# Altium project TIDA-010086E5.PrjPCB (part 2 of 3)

## Sheet TIDA-010086E5_ControlCard.SchDoc
size 431 x 279 mm; Date: Not shown in title block; ApprovedBy: Not shown in title block; CheckedBy: Not shown in title block; Author: Not shown in title block; CompanyName: Not shown in title block; DrawnBy: Battery test; Engineer: Not shown in title block; Organization: Not shown in title block; Address1: Not shown in title block; Address2: Not shown in title block; Address3: Not shown in title block; Address4: Not shown in title block; DocumentNumber: 6; Revision: Use project parameter SCH_Rev; SheetNumber: 6; SheetTotal: 8; PageSetup: Record=PageOptions¦CenterHorizontal=True¦CenterVertical=True¦PrintScale=1.00¦XCorrection=1.00¦YCorrection=1.00¦PrintKind=0¦BorderSize=5000000¦LeftOffset=0¦BottomOffset=0¦Orientation=2¦PaperLength=1000¦PaperWidth=1000¦Scale=100¦PaperSource=15¦PrintQuality=600¦MediaType=1¦DitherType=10¦PaperKind=Letter¦PrintScaleMode=1
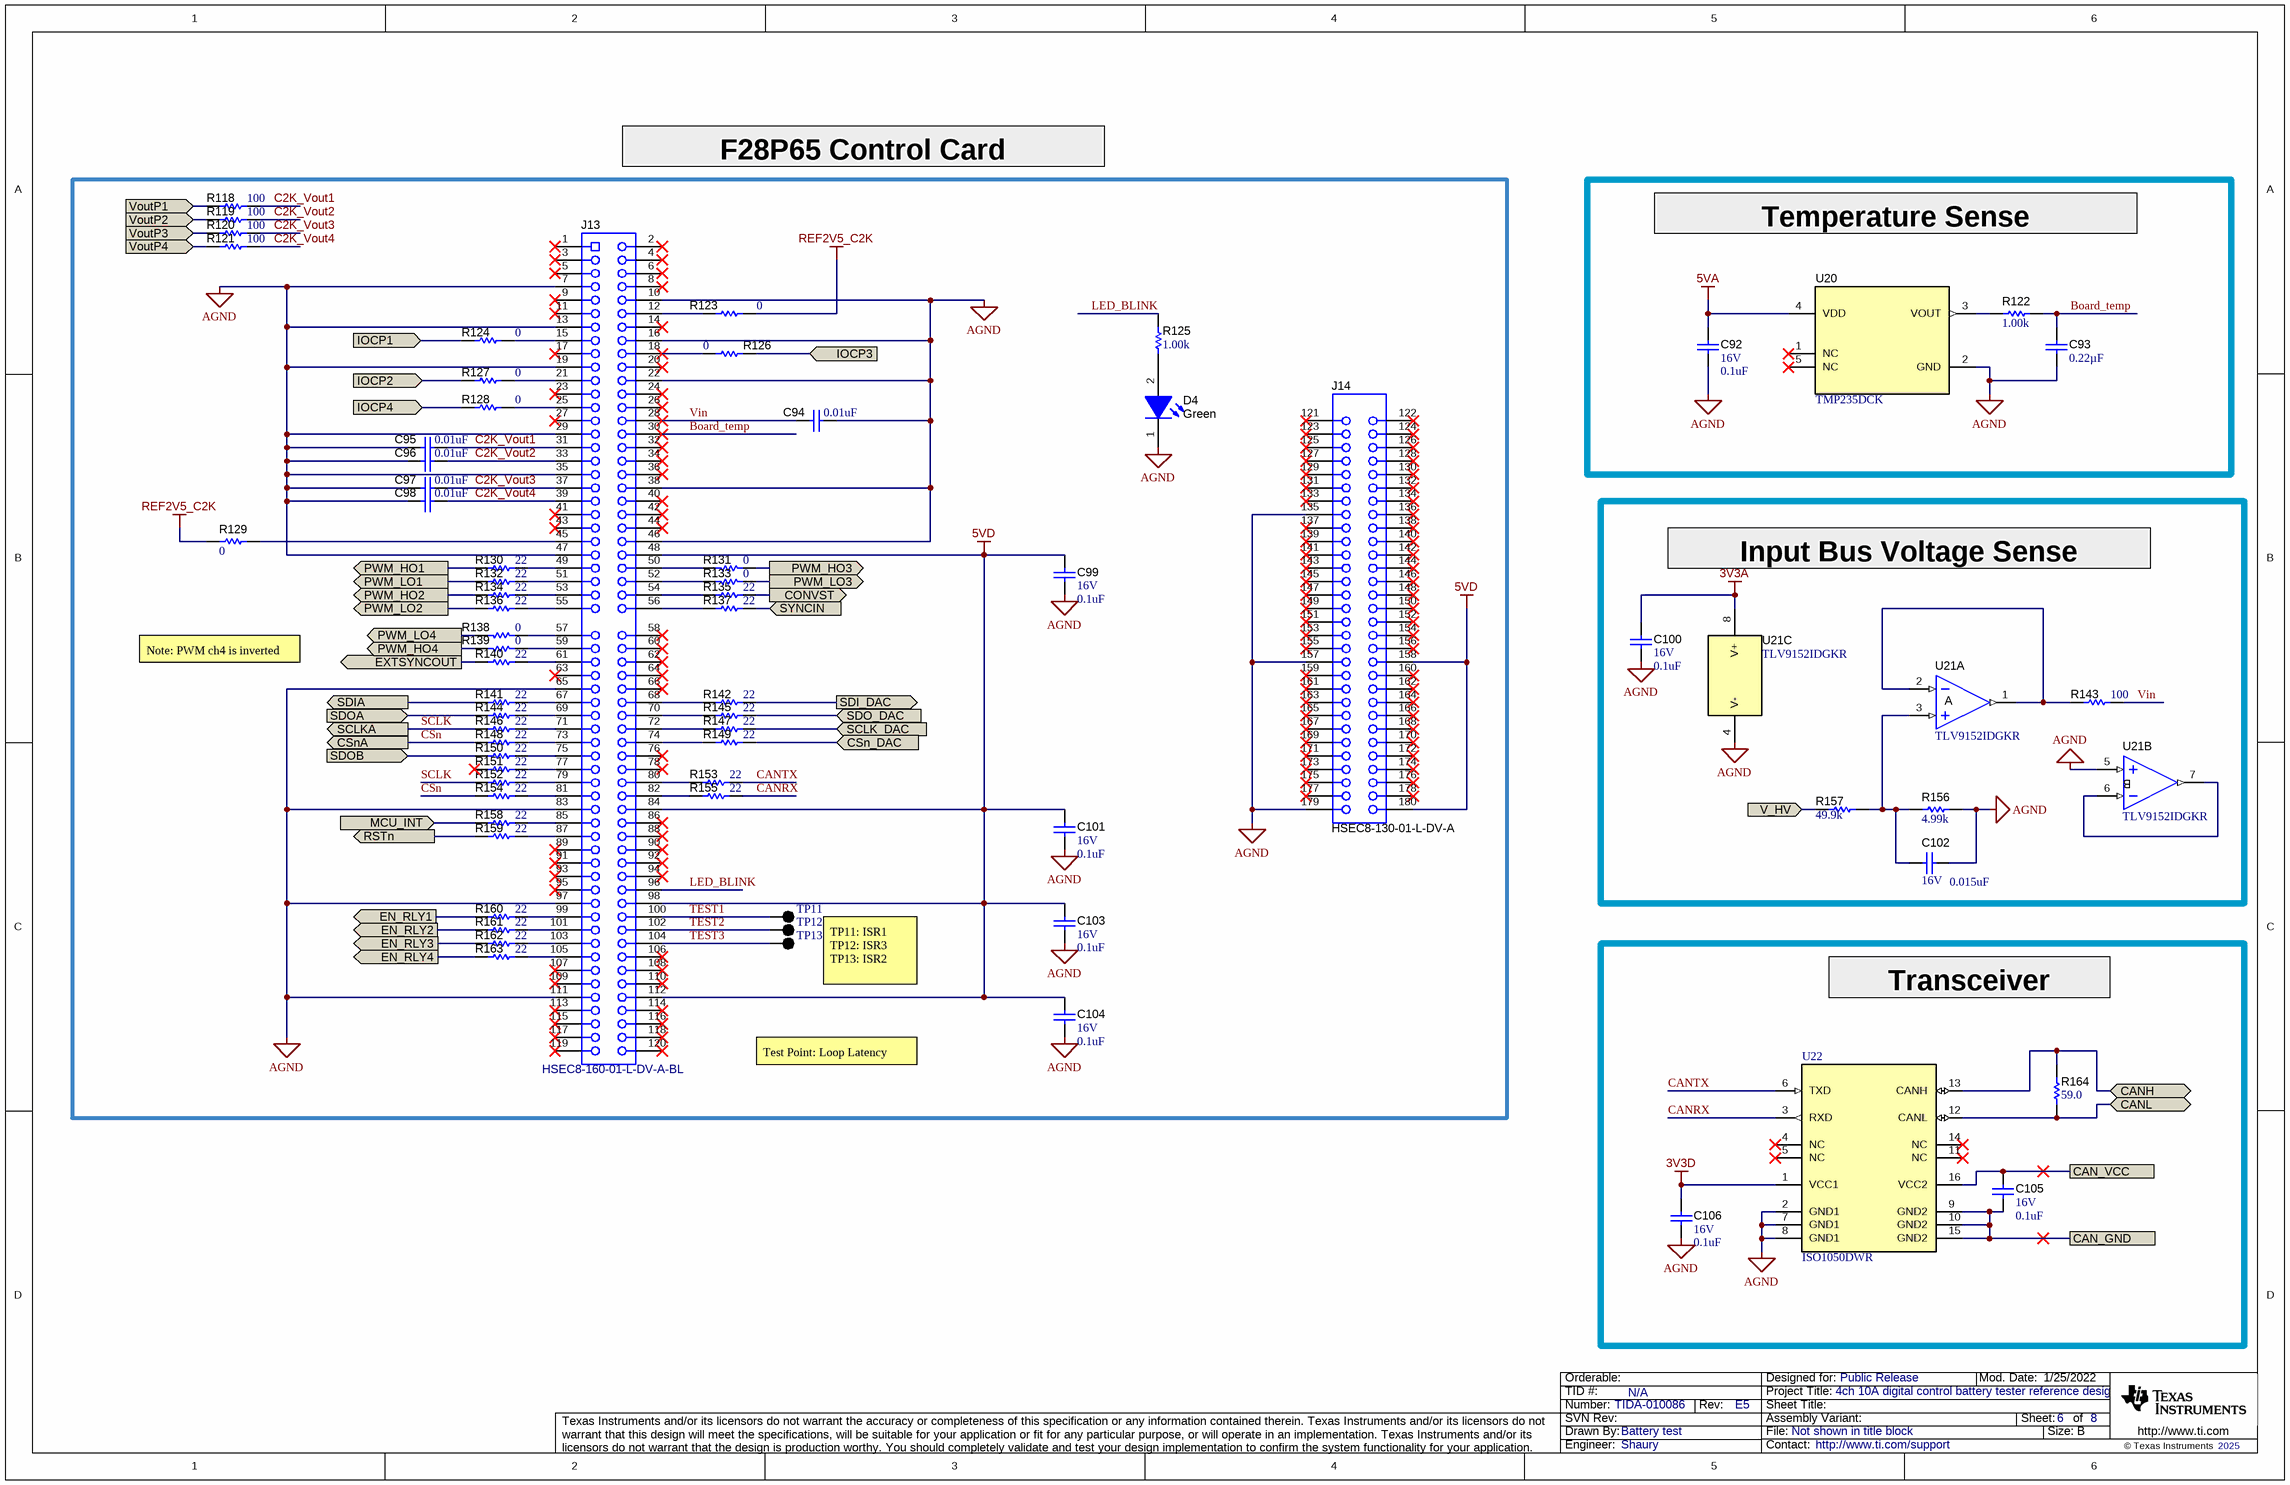
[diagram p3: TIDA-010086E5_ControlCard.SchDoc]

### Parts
C92  VDC_V: 16V  ValueDisplayed: 0.1uF  [0402]  (hidden comment: GRM155R61C104KA88D)
C93  ValueDisplayed: 0.22µF  [0402]  (hidden comment: GCM155R71C224KE02D)
C94  ValueDisplayed: 0.01uF  [0402]  (hidden comment: GRM155R71C103KA01D)
C95  ValueDisplayed: 0.01uF  [0402]  (hidden comment: GRM155R71C103KA01D)
C96  ValueDisplayed: 0.01uF  [0402]  (hidden comment: GRM155R71C103KA01D)
C97  ValueDisplayed: 0.01uF  [0402]  (hidden comment: GRM155R71C103KA01D)
C98  ValueDisplayed: 0.01uF  [0402]  (hidden comment: GRM155R71C103KA01D)
C99  VDC_V: 16V  ValueDisplayed: 0.1uF  [0402]  (hidden comment: GRM155R61C104KA88D)
C100  VDC_V: 16V  ValueDisplayed: 0.1uF  [0402]  (hidden comment: GRM155R61C104KA88D)
C101  VDC_V: 16V  ValueDisplayed: 0.1uF  [0402]  (hidden comment: GRM155R61C104KA88D)
C102  VDC_V: 16V  ValueDisplayed: 0.015uF  [0402]  (hidden comment: GRM155R71C153KA01D)
C103  VDC_V: 16V  ValueDisplayed: 0.1uF  [0402]  (hidden comment: GRM155R61C104KA88D)
C104  VDC_V: 16V  ValueDisplayed: 0.1uF  [0402]  (hidden comment: GRM155R61C104KA88D)
C105  VDC_V: 16V  ValueDisplayed: 0.1uF  [0402]  (hidden comment: GRM155R61C104KA88D)
C106  VDC_V: 16V  ValueDisplayed: 0.1uF  [0402]  (hidden comment: GRM155R61C104KA88D)
D4  value Green  [WL-SMCW_GREEN]  (hidden comment: 150060VS75000)
J13  HSEC8-160-01-L-DV-A-BL  [controlCARD-120HSEC]
J14  HSEC8-130-01-L-DV-A  [controlCARD-180HSEC-60pinAddon]
R118  ValueDisplayed: 100  [0402]  (hidden comment: CRCW0402100RFKED)
R119  ValueDisplayed: 100  [0402]  (hidden comment: CRCW0402100RFKED)
R120  ValueDisplayed: 100  [0402]  (hidden comment: CRCW0402100RFKED)
R121  ValueDisplayed: 100  [0402]  (hidden comment: CRCW0402100RFKED)
R122  ValueDisplayed: 1.00k  [0402]  (hidden comment: ERA-2AEB102X)
R123  ValueDisplayed: 0  [0402]  (hidden comment: CRCW04020000Z0ED)
R124  ValueDisplayed: 0  [0402]  (hidden comment: CRCW04020000Z0ED)
R125  ValueDisplayed: 1.00k  [0402]  (hidden comment: ERA-2AEB102X)
R126  ValueDisplayed: 0  [0402]  (hidden comment: CRCW04020000Z0ED)
R127  ValueDisplayed: 0  [0402]  (hidden comment: CRCW04020000Z0ED)
R128  ValueDisplayed: 0  [0402]  (hidden comment: CRCW04020000Z0ED)
R129  ValueDisplayed: 0  [0402]  (hidden comment: CRCW04020000Z0ED)
R130  ValueDisplayed: 22  [0402]  (hidden comment: CRCW040222R0JNED)
R131  ValueDisplayed: 0  [0402]  (hidden comment: CRCW04020000Z0ED)
R132  ValueDisplayed: 22  [0402]  (hidden comment: CRCW040222R0JNED)
R133  ValueDisplayed: 0  [0402]  (hidden comment: CRCW04020000Z0ED)
R134  ValueDisplayed: 22  [0402]  (hidden comment: CRCW040222R0JNED)
R135  ValueDisplayed: 22  [0402]  (hidden comment: CRCW040222R0JNED)
R136  ValueDisplayed: 22  [0402]  (hidden comment: CRCW040222R0JNED)
R137  ValueDisplayed: 22  [0402]  (hidden comment: CRCW040222R0JNED)
R138  ValueDisplayed: 0  [0402]  (hidden comment: CRCW04020000Z0ED)
R139  ValueDisplayed: 0  [0402]  (hidden comment: CRCW04020000Z0ED)
R140  ValueDisplayed: 22  [0402]  (hidden comment: CRCW040222R0JNED)
R141  ValueDisplayed: 22  [0402]  (hidden comment: CRCW040222R0JNED)
R142  ValueDisplayed: 22  [0402]  (hidden comment: CRCW040222R0JNED)
R143  ValueDisplayed: 100  [0402]  (hidden comment: CRCW0402100RFKED)
R144  ValueDisplayed: 22  [0402]  (hidden comment: CRCW040222R0JNED)
R145  ValueDisplayed: 22  [0402]  (hidden comment: CRCW040222R0JNED)
R146  ValueDisplayed: 22  [0402]  (hidden comment: CRCW040222R0JNED)
R147  ValueDisplayed: 22  [0402]  (hidden comment: CRCW040222R0JNED)
R148  ValueDisplayed: 22  [0402]  (hidden comment: CRCW040222R0JNED)
R149  ValueDisplayed: 22  [0402]  (hidden comment: CRCW040222R0JNED)
R150  ValueDisplayed: 22  [0402]  (hidden comment: CRCW040222R0JNED)
R151  ValueDisplayed: 22  [0402]  (hidden comment: CRCW040222R0JNED)
R152  ValueDisplayed: 22  [0402]  (hidden comment: CRCW040222R0JNED)
R153  ValueDisplayed: 22  [0402]  (hidden comment: CRCW040222R0JNED)
R154  ValueDisplayed: 22  [0402]  (hidden comment: CRCW040222R0JNED)
R155  ValueDisplayed: 22  [0402]  (hidden comment: CRCW040222R0JNED)
R156  ValueDisplayed: 4.99k  [0603]  (hidden comment: CRCW06034K99FKEAC)
R157  ValueDisplayed: 49.9k  [0603]  (hidden comment: CRCW060349K9FKEA)
R158  ValueDisplayed: 22  [0402]  (hidden comment: CRCW040222R0JNED)
R159  ValueDisplayed: 22  [0402]  (hidden comment: CRCW040222R0JNED)
R160  ValueDisplayed: 22  [0402]  (hidden comment: CRCW040222R0JNED)
R161  ValueDisplayed: 22  [0402]  (hidden comment: CRCW040222R0JNED)
R162  ValueDisplayed: 22  [0402]  (hidden comment: CRCW040222R0JNED)
R163  ValueDisplayed: 22  [0402]  (hidden comment: CRCW040222R0JNED)
R164  ValueDisplayed: 59.0  [1206]  (hidden comment: ERJ-8ENF59R0V)
TP11  5001  [Keystone5001]  (value not drawn)
TP12  5001  [Keystone5001]  (value not drawn)
TP13  5001  [Keystone5001]  (value not drawn)
U20  TMP235DCK  [DCK0005A_N]
U21  TLV9152IDGKR  [DGK0008A_N]  (parts A,B,C of 3)
U22  ISO1050DWR  [DW0016B_HV]

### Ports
CAN_GND, CAN_VCC, CANH (bidir), CANL (bidir), CONVST (out), CSn_DAC (in), CSnA (out), EN_RLY1 (out), EN_RLY2 (out), EN_RLY3 (out), EN_RLY4 (out), EXTSYNCOUT (out), IOCP1 (in), IOCP2 (in), IOCP3 (in), IOCP4 (in), MCU_INT (in), PWM_HO1 (out), PWM_HO2 (out), PWM_HO3 (out), PWM_HO4 (out), PWM_LO1 (out), PWM_LO2 (out), PWM_LO3 (out), PWM_LO4 (out), RSTn (out), SCLK_DAC (in), SCLKA (out), SDI_DAC (out), SDIA (out), SDO_DAC (in), SDOA (in), SDOB (in), SYNCIN (in), V_HV (in), VoutP1 (in), VoutP2 (in), VoutP3 (in), VoutP4 (in)

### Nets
3V3A: C100.2 U21.8(V+)
3V3D: C106.2 U22.1(VCC1)
5VA: C92.2 U20.4(VDD)
5VD: C99.2 C101.2 C103.2 C104.2 J13.48 J13.84 J13.98 J13.112 J14.158 J14.180
AGND: C92.1 C93.2 C94.2 C95.1 C96.1 C97.1 C98.1 C99.1 C100.1 C101.1 C102.2 C103.1 C104.1 C106.1 D4.1(K) J13.7 J13.10 J13.13 J13.16 J13.19 J13.22 J13.29 J13.35 J13.38 J13.46 J13.47 J13.65 J13.83 J13.97 J13.111 J14.135 J14.157 J14.179 R156.2 U20.2(GND) U21.4(V-) U21.5(IN+) U22.2(GND1) U22.7(GND1) U22.8(GND1)
REF2V5_C2K: R123.1 R129.2
Board_temp: C93.1 J13.30 R122.1
C2K_Vout1: C95.2 J13.31 R118.2
C2K_Vout2: C96.2 J13.33 R119.2
C2K_Vout3: C97.2 J13.37 R120.2
C2K_Vout4: C98.2 J13.39 R121.2
CAN_GND: C105.1 U22.9(GND2) U22.10(GND2) U22.15(GND2) ; port CAN_GND
CAN_VCC: C105.2 U22.16(VCC2) ; port CAN_VCC
CANH: R164.2 U22.13(CANH) ; port CANH
CANL: R164.1 U22.12(CANL) ; port CANL
CANRX: R155.2 U22.3(RXD)
CANTX: R153.2 U22.6(TXD)
CONVST: R135.2 ; port CONVST
CSn: R148.1 R154.1 ; port CSnA  [project net CSnA]
CSn_DAC: R149.2 ; port CSn_DAC
EN_RLY1: R160.1 ; port EN_RLY1
EN_RLY2: R161.1 ; port EN_RLY2
EN_RLY3: R162.1 ; port EN_RLY3
EN_RLY4: R163.1 ; port EN_RLY4
EXTSYNCOUT: R140.2 ; port EXTSYNCOUT
IOCP1: R124.2 ; port IOCP1
IOCP2: R127.2 ; port IOCP2
IOCP3: R126.2 ; port IOCP3
IOCP4: R128.2 ; port IOCP4
LED_BLINK: J13.96 R125.2
MCU_INT: R158.1 ; port MCU_INT
PWM_HO1: R130.1 ; port PWM_HO1
PWM_HO2: R134.1 ; port PWM_HO2
PWM_HO3: R131.2 ; port PWM_HO3
PWM_HO4: R139.2 ; port PWM_HO4
PWM_LO1: R132.1 ; port PWM_LO1
PWM_LO2: R136.1 ; port PWM_LO2
PWM_LO3: R133.2 ; port PWM_LO3
PWM_LO4: R138.2 ; port PWM_LO4
RSTn: R159.1 ; port RSTn
SCLK: R146.1 R152.1 ; port SCLKA  [project net SCLKA]
SCLK_DAC: R147.2 ; port SCLK_DAC
SDI_DAC: R142.2 ; port SDI_DAC
SDIA: R141.1 ; port SDIA
SDO_DAC: R145.2 ; port SDO_DAC
SDOA: R144.1 ; port SDOA
SDOB: R150.1 ; port SDOB
SYNCIN: R137.2 ; port SYNCIN
TEST1: J13.100 TP11.1
TEST2: J13.102 TP12.1
TEST3: J13.104 TP13.1
V_HV: R157.2 ; port V_HV
Vin: C94.1 J13.28 R143.2
VoutP1: R118.1 ; port VoutP1
VoutP2: R119.1 ; port VoutP2
VoutP3: R120.1 ; port VoutP3
VoutP4: R121.1 ; port VoutP4
NetC102_1: C102.1 R156.1 R157.1 U21.3(IN+)
NetD4_2: D4.2(A) R125.1
NetJ13_12: J13.12 R123.2
NetJ13_15: J13.15 R124.1
NetJ13_18: J13.18 R126.1
NetJ13_21: J13.21 R127.1
NetJ13_25: J13.25 R128.1
NetJ13_45: J13.45 R129.1
NetJ13_49: J13.49 R130.2
NetJ13_50: J13.50 R131.1
NetJ13_51: J13.51 R132.2
NetJ13_52: J13.52 R133.1
NetJ13_53: J13.53 R134.2
NetJ13_54: J13.54 R135.1
NetJ13_55: J13.55 R136.2
NetJ13_56: J13.56 R137.1
NetJ13_57: J13.57 R138.1
NetJ13_59: J13.59 R139.1
NetJ13_61: J13.61 R140.1
NetJ13_67: J13.67 R141.2
NetJ13_68: J13.68 R142.1
NetJ13_69: J13.69 R144.2
NetJ13_70: J13.70 R145.1
NetJ13_71: J13.71 R146.2
NetJ13_72: J13.72 R147.1
NetJ13_73: J13.73 R148.2
NetJ13_74: J13.74 R149.1
NetJ13_75: J13.75 R150.2
NetJ13_77: J13.77 R151.2
NetJ13_79: J13.79 R152.2
NetJ13_80: J13.80 R153.1
NetJ13_81: J13.81 R154.2
NetJ13_82: J13.82 R155.1
NetJ13_85: J13.85 R158.2
NetJ13_87: J13.87 R159.2
NetJ13_99: J13.99 R160.2
NetJ13_101: J13.101 R161.2
NetJ13_103: J13.103 R162.2
NetJ13_105: J13.105 R163.2
NetR122_2: R122.2 U20.3(VOUT)
NetR143_1: R143.1 U21.1(OUT) U21.2(IN-)
NetU21_6: U21.6(IN-) U21.7(OUT)

Not connected (* = marked no-connect by the designer): J13 1* 2* 3* 4* 5* 6* 8* 9* 11* 14* 17* 20* 23* 24* 26* 27* 32* 34* 36* 40* 41* 42* 43* 44* 58* 60* 62* 63* 64* 66* 76* 78* 86* 88* 89* 90* 91* 92* 93* 94* 95* 106* 107* 108* 109* 110* 113* 114* 115* 116* 117* 118* 119* 120*; J14 121* 122* 123* 124* 125* 126* 127* 128* 129* 130* 131* 132* 133* 134* 136* 137* 138* 139* 140* 141* 142* 143* 144* 145* 146* 147* 148* 149* 150* 151* 152* 153* 154* 155* 156* 159* 160* 161* 162* 163* 164* 165* 166* 167* 168* 169* 170* 171* 172* 173* 174* 175* 176* 177* 178*; R151 1*; U20 1(NC)* 5(NC)*; U22 4(NC)* 5(NC)* 11(NC)* 14(NC)*

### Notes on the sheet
- F28P65 Control Card
- Temperature Sense
- Input Bus Voltage Sense
- Note: PWM ch4 is inverted
- TP11: ISR1
  TP12: ISR3
  TP13: ISR2
- Transceiver
- Test Point: Loop Latency

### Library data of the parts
C92 C99-C101 C103-C106 = CMP-0006591-2: CAP, CERM, 0.1 uF, 16 V, +/- 10%, X5R, 0402; Manufacturer: MuRata; TaMin_C: -55°C; Polarized: N; SizeAreaWB_mm2: 3; Value1: Unknown; U/M: EA; Value: 0.1uF; TaMax_C: 85°C; SizeZ_mm: 0.6; SizeX_mm: 1; SizeY_mm: 0.5; Cap_F: 100nF; AEC Category: Q200
C93 = CMP-0078265-1: CAP, CERM, 0.22 µF, 16 V,+/- 10%, X7R, AEC-Q200 Grade 1, 0402; Manufacturer: MuRata; TaMin_C: -55°C; Polarized: N; SizeAreaWB_mm2: 3; U/M: EA; Value: 0.22uF; TaMax_C: 125°C; SizeZ_mm: 0.6; SizeX_mm: 1; SizeY_mm: 0.5; Value2: 16V; AEC Qualified: Y; Cap_F: 220nF; AEC Category: Q200
C94-C98 = CMP-0006639-2: CAP, CERM, 0.01 uF, 16 V, +/- 10%, X7R, 0402; Manufacturer: MuRata; TaMin_C: -55°C; Polarized: N; SizeAreaWB_mm2: 3; Value1: Unknown; U/M: EA; Value: 0.01uF; TaMax_C: 125°C; SizeZ_mm: 0.6; SizeX_mm: 1; SizeY_mm: 0.5; Value2: 16V; Cap_F: 10nF; AEC Category: Q200
C102 = CMP-0006644-2: CAP, CERM, 0.015 uF, 16 V, +/- 10%, X7R, 0402; Manufacturer: MuRata; TaMin_C: -55°C; Polarized: N; SizeAreaWB_mm2: 3; Value1: Unknown; U/M: EA; TaMax_C: 125°C; SizeZ_mm: 0.6; SizeX_mm: 1; SizeY_mm: 0.5; Cap_F: 15nF; AEC Category: Q200
D4 = CMP-0002894-2: LED, Green, SMD; Manufacturer: Wurth Elektronik; Type: AlInGaP; Vf_V: 2V; Io_A: 20mA; Value1: W
J13 = CMP-0003814-2: C2000 controlCARD-120HSEC connector, SMT; Manufacturer: Samtec; Note: The pin numbering does not match Samtec datasheet
J14 = CMP-0003859-2: C2000 controlCARD-180HSEC (60-pin addon) connector, SMT; Manufacturer: Samtec; Note: The pin numbering does not match Samtec datasheet
R118-R121 R143 = CMP-0025951-3: RES, 100, 1%, 0.063 W, AEC-Q200 Grade 0, 0402; Manufacturer: Vishay-Dale; Power_W: 63mW; TempCo: 100 ppm/C; Value_Code: 100R; Value: 100; EIA_Code: E96; SizeX_mm: 1; SizeY_mm: 0.5; SizeZ_mm: 0.6; Value2: 0.063W; AEC Qualified: Y; VDC_V: 50V; AEC Category: Q200; AEC Grade: 0
R122 R125 = CMP-0026770-1: RES, 1.00 k, 0.1%, 0.063 W, 0402; Manufacturer: Panasonic; Power_W: 63mW; TempCo: 25 ppm/C; Value_Code: 1k00; U/M: EA; Value: 1.00k; EIA_Code: E192; Res_ohm: 1k; SizeX_mm: 1; SizeY_mm: 0.5; SizeZ_mm: 0.6; Value2: 0.063W; VDC_V: 50V; AEC Category: Q200
R123 R124 R126-R129 R131 R133 R138 R139 = CMP-0026822-3: RES, 0, 5%, 0.063 W, AEC-Q200 Grade 0, 0402; Manufacturer: Vishay-Dale; Value: 0; Value_Code: 0000; Power_W: 63mW; Value2: 0.063W; VDC_V: 50V; TempCo: 200 ppm/C; SizeArea_mm2: 0.5; SizeX_mm: 1; SizeZ_mm: 0.6; EIA_Code: E24; AEC Category: Q200; AEC Qualified: Y
R130 R132 R134-R137 R140-R142 R144-R155 R158-R163 = CMP-0026880-3: RES, 22, 5%, 0.063 W, AEC-Q200 Grade 0, 0402; Manufacturer: Vishay-Dale; Power_W: 63mW; TempCo: 200 ppm/C; Value_Code: 22R0; Value: 22; EIA_Code: E24; SizeX_mm: 1; SizeY_mm: 0.5; SizeZ_mm: 0.6; Value2: 0.063W; AEC Qualified: Y; VDC_V: 50V; AEC Category: Q200; AEC Grade: 0
R156 = CMP-0082533-1: RES, 4.99 k, 1%, 0.1 W, 0603; Manufacturer: Vishay-Dale; Power_W: 100mW; TempCo: 100 ppm/C; SizeAreaWB_mm2: 4.68; Value_Code: 4k99; Value: 4.99k; EIA_Code: E96; SizeX_mm: 1.6; SizeY_mm: 0.8; SizeZ_mm: 1; Value2: 0.1W; SizeArea_mm2: 1.28; AEC Qualified: N; VDC_V: 75V; AEC Category: Q200
R157 = CMP-0022447-4: RES, 49.9 k, 1%, 0.1 W, AEC-Q200 Grade 0, 0603; Manufacturer: Vishay-Dale; Power_W: 100mW; TempCo: 100 ppm/C; Value_Code: 49k9; Value: 49.9k; EIA_Code: E96; SizeX_mm: 1.6; SizeY_mm: 0.8; SizeZ_mm: 1; Value2: 0.1W; SizeArea_mm2: 1.28; AEC Qualified: Y; VDC_V: 75V; AEC Category: Q200; AEC Grade: 0
R164 = CMP-0017667-3: RES, 59.0, 1%, 0.25 W, AEC-Q200 Grade 0, 1206; Manufacturer: Panasonic; Power_W: 250mW; TempCo: 100 ppm/C; Value_Code: 59R0; Value: 59.0; EIA_Code: E96; Res_ohm: 59; SizeX_mm: 3.2; SizeY_mm: 1.6; SizeZ_mm: 1.35; Value2: 0.25W; SizeArea_mm2: 5.12; AEC Qualified: Y; VDC_V: 200V; AEC Category: Q200; AEC Grade: 0; SizeAreaWB_mm2: 10.92
TP11-TP13 = CMP-0055138-2: Test Point, Miniature, Black, TH; Manufacturer: Keystone Electronics; ContactFinish: Silver; Green_Lifecycle: Active; Green_REACh: Passed; CNHeader: FALSE; CT: TRUE
U20 = CMP-0013250-3: TMP235DCK, DCK0005A (SOT-5); Manufacturer: Texas Instruments; SizeX_mm: 2.1; SizeY_mm: 2.0; CompType: IC; SizeZ_mm: 1.1; SizeArea_mm2: 4.2; SizeAreaWB_mm2: 9.3; AEC Category: Q200; AEC Qualified: N
U21 = CMP-0100002-2: 5MHz, 15V/us High Slew-Rate, RRIO Op Amp, DGK0008A (VSSOP-8); Alternate Manufacturer: Texas Instruments; AEC Qualified: N; SizeX_mm: 4.9; AEC Category: Q200; SizeZ_mm: 1.1; SizeAreaWB_mm2: 23.6; SizeY_mm: 3; Rating: Catalog; SizeArea_mm2: 14.7; CompType: IC
U22 = CMP-0033359-4: Isolated 5 V CAN Transceiver, DW0016B (SOIC-16); Manufacturer: Texas Instruments; SizeArea_mm2: 107.12; SizeZ_mm: 2.65; Drivers Per Package: 1; SizeY_mm: 10.3; SizeX_mm: 10.4; SizeAreaWB_mm2: 152.52; CompType: IC; AEC Category: Q200; Rating: Catalog; AEC Qualified: N; Isolated: Yes

## Sheet TIDA-010086E5_Hardware.SchDoc
size 431 x 279 mm; Date: Not shown in title block; ApprovedBy: Not shown in title block; CheckedBy: Not shown in title block; Author: Not shown in title block; CompanyName: Not shown in title block; DrawnBy: Battery test; Engineer: Not shown in title block; Organization: Not shown in title block; Address1: Not shown in title block; Address2: Not shown in title block; Address3: Not shown in title block; Address4: Not shown in title block; DocumentNumber: 8; Revision: Use project parameter SCH_Rev; SheetNumber: 8; SheetTotal: 8; PageSetup: Record=PageOptions¦CenterHorizontal=True¦CenterVertical=True¦PrintScale=1.00¦XCorrection=1.00¦YCorrection=1.00¦PrintKind=0¦BorderSize=5000000¦LeftOffset=0¦BottomOffset=0¦Orientation=2¦PaperLength=1000¦PaperWidth=1000¦Scale=100¦PaperSource=15¦PrintQuality=600¦MediaType=1¦DitherType=10¦PaperKind=Letter¦PrintScaleMode=1
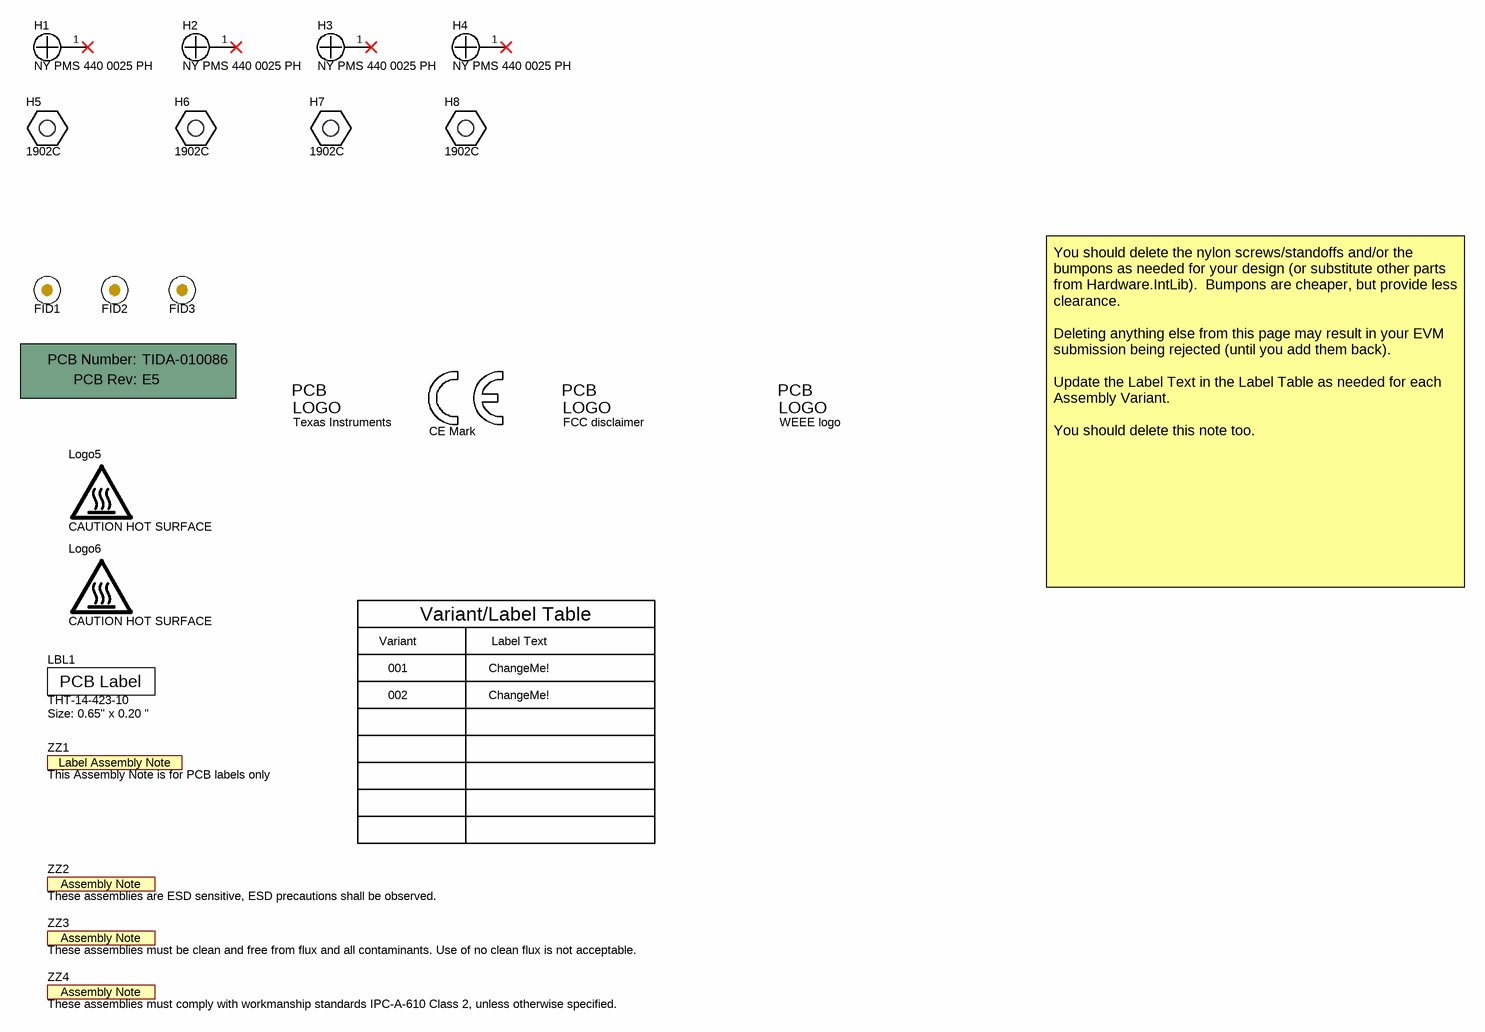
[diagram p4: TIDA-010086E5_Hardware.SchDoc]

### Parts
!PCB1  Printed Circuit Board  (value not drawn)  (mechanical)
FID1  Fiducial  [Fiducial10-20]  (value not drawn)
FID2  Fiducial  [Fiducial10-20]  (value not drawn)
FID3  Fiducial  [Fiducial10-20]  (value not drawn)
H1  NY PMS 440 0025 PH  [NY PMS 440 0025 PH]
H2  NY PMS 440 0025 PH  [NY PMS 440 0025 PH]
H3  NY PMS 440 0025 PH  [NY PMS 440 0025 PH]
H4  NY PMS 440 0025 PH  [NY PMS 440 0025 PH]
H5  1902C  [Keystone_1902C]
H6  1902C  [Keystone_1902C]
H7  1902C  [Keystone_1902C]
H8  1902C  [Keystone_1902C]
LBL1  THT-14-423-10  Note: Size: 0.65" x 0.20 "  [Label_650x200]
Logo1  CE Mark  [CE_Mark_5mm]  (no BOM)
Logo2  Texas Instruments  [TI_Stacked_Overlay_Small]  (no BOM)
Logo3  FCC disclaimer  [FCC_disclaimer]  (no BOM)
Logo4  WEEE logo  [WEEE_Minimum]  (no BOM)
Logo5  CAUTION HOT SURFACE  [IEC_HotSurface_Large]  (no BOM)
Logo6  CAUTION HOT SURFACE  [IEC_HotSurface_Large]  (no BOM)
ZZ1  This Assembly Note is for PCB labels only  [AssemblyNoteLabel]  (no BOM)
ZZ2  These assemblies are ESD sensitive, ESD precautions shall be observed.  [AssemblyNote]  (no BOM)
ZZ3  These assemblies must be clean and free from flux and all contaminants. Use of no clean flux is not acceptable.  [AssemblyNote]  (no BOM)
ZZ4  These assemblies must comply with workmanship standards IPC-A-610 Class 2, unless otherwise specified.  [AssemblyNote]  (no BOM)

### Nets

Not connected (* = marked no-connect by the designer): H1 1*; H2 1*; H3 1*; H4 1*

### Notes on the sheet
- Variant
- Variant/Label Table
- Label Text
- You should delete the nylon screws/standoffs and/or the bumpons as needed for your design (or substitute other parts from Hardware.IntLib).  Bumpons are cheaper, but provide less clearance.
  Deleting anything else from this page may result in your EVM submission being rejected (until you add them back).
  Update the Label Text in the Label Table as needed for each Assembly Variant.
  You should delete this note too.
- 001
- 002
- ChangeMe!

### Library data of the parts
!PCB1 = CMP-0003618-2: Manufacturer: Any; PartNumber: TIDA-010086
FID1-FID3 = CMP-0077181-1: Fiducial mark.  There is nothing to buy or mount.
H1-H4 = CMP-0003617-1: Machine Screw, Round, #4-40 x 1/4, Nylon, Philips panhead; Manufacturer: B&F Fastener Supply; CompType: Hardware
H5-H8 = CMP-0003610-1: Standoff, Hex, 0.5"L #4-40 Nylon; Manufacturer: Keystone; CompType: Hardware
LBL1 = CMP-0003625-1: Thermal Transfer Printable Labels, 0.650" W x 0.200" H - 10,000 per roll; Manufacturer: Brady; CompType: Label
Logo1 = CMP-0074844-1: SymbolCreator: a0412235
Logo2 = CMP-0074838-1: Texas Instrument Corporate Signature; SymbolCreator: a0412235; Lib Reference: TI_Logo; Library Reference: Logo
Logo3 = CMP-0074847-1: FCC_disclaimer; Library Reference: Logo
Logo4 = CMP-0074769-3: Manufacturer: Texas Instruments; CompType: IC; AEC Category: Q200
Logo5 Logo6 = CMP-0074837-2: IEC 61010-1 Hot Surface Warning; Manufacturer: Texas Instruments; CompType: IC; AEC Category: Q200; SymbolCreator: a0412235
ZZ1 = CMP-0003616-3
ZZ2 = CMP-0077236-1
ZZ3 = CMP-0077237-1
ZZ4 = CMP-0077238-1

## Sheet TIDA-010086E5_V_I_Sense.SchDoc
size 431 x 279 mm; Date: Not shown in title block; ApprovedBy: Not shown in title block; CheckedBy: Not shown in title block; Author: Not shown in title block; CompanyName: Not shown in title block; DrawnBy: Battery test; Engineer: Not shown in title block; Organization: Not shown in title block; Address1: Not shown in title block; Address2: Not shown in title block; Address3: Not shown in title block; Address4: Not shown in title block; DocumentNumber: 4; Revision: Use project parameter SCH_Rev; SheetNumber: 4; SheetTotal: 8; PageSetup: Record=PageOptions¦CenterHorizontal=True¦CenterVertical=True¦PrintScale=1.00¦XCorrection=1.00¦YCorrection=1.00¦PrintKind=0¦BorderSize=5000000¦LeftOffset=0¦BottomOffset=0¦Orientation=2¦PaperLength=1000¦PaperWidth=1000¦Scale=100¦PaperSource=15¦PrintQuality=600¦MediaType=1¦DitherType=10¦PaperKind=Letter¦PrintScaleMode=1
Used 4 times, as channels Sns1, Sns2, Sns3, Sns4. Parts and nets are listed once, with the designators drawn on the sheet.
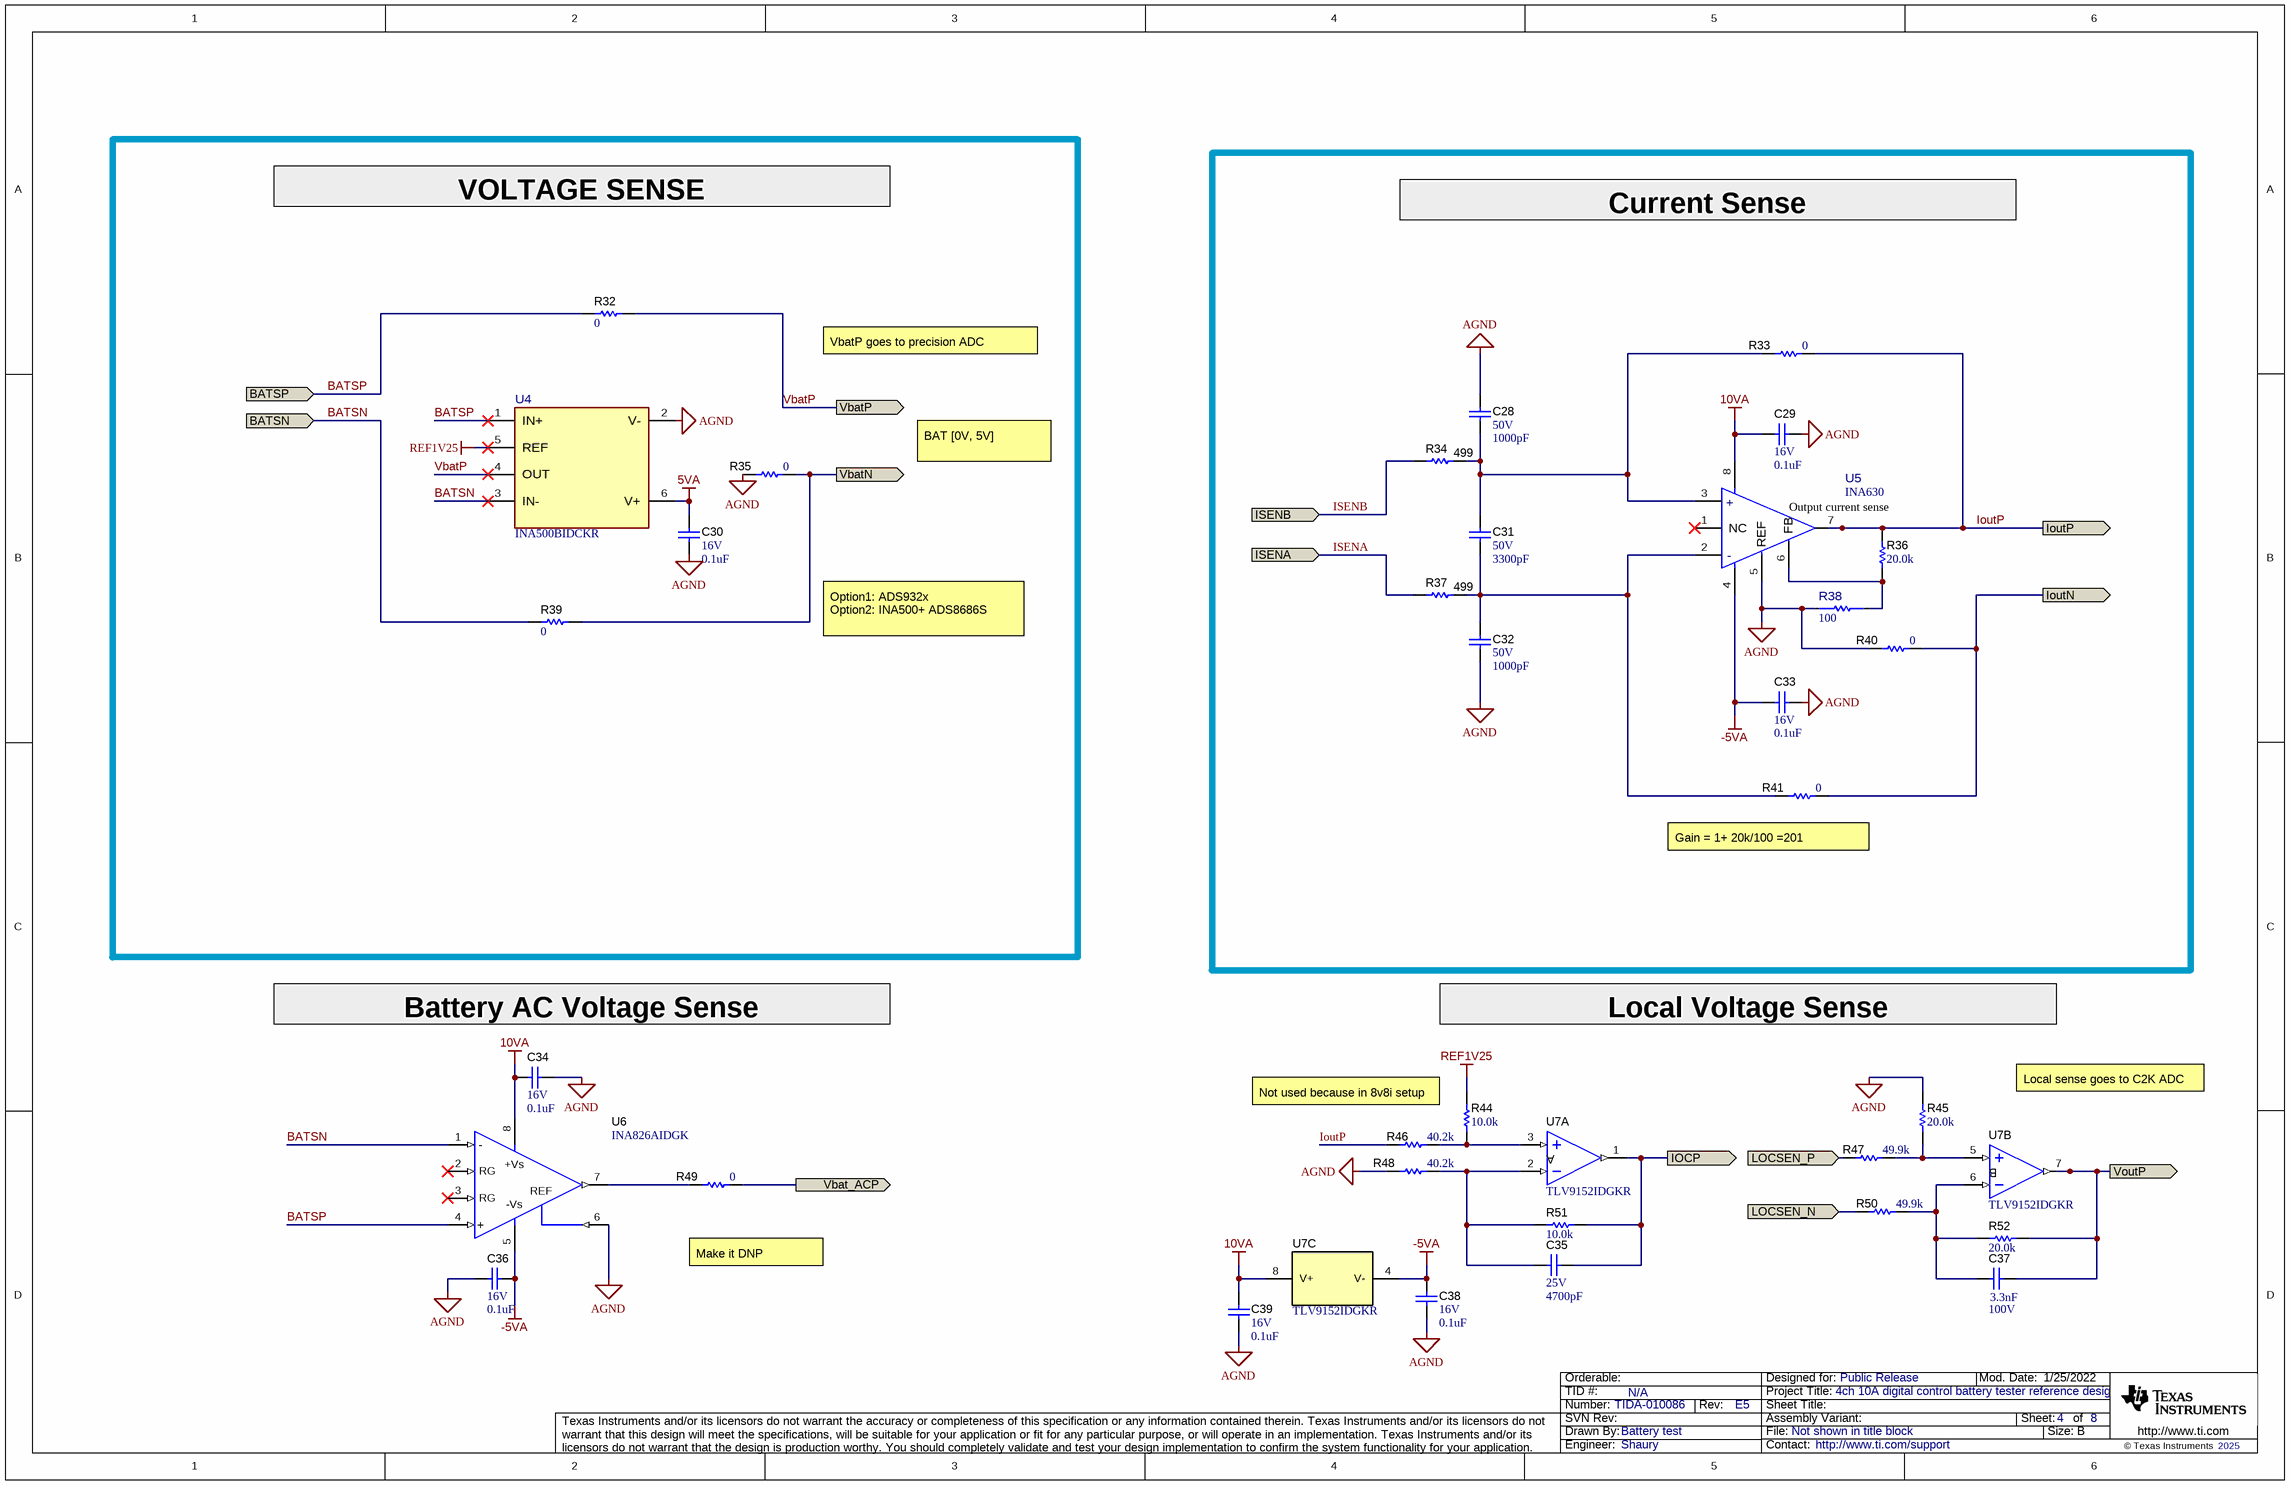
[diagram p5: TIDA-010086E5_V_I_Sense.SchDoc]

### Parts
C28  VDC_V: 50V  ValueDisplayed: 1000pF  [0402]  (hidden comment: GRM1555C1H102JA01D)
C29  VDC_V: 16V  ValueDisplayed: 0.1uF  [0402]  (hidden comment: GRM155R61C104KA88D)
C30  VDC_V: 16V  ValueDisplayed: 0.1uF  [0402]  (hidden comment: GRM155R61C104KA88D)
C31  VDC_V: 50V  ValueDisplayed: 3300pF  [0603]  (hidden comment: GRM1885C1H332JA01D)
C32  VDC_V: 50V  ValueDisplayed: 1000pF  [0402]  (hidden comment: GRM1555C1H102JA01D)
C33  VDC_V: 16V  ValueDisplayed: 0.1uF  [0402]  (hidden comment: GRM155R61C104KA88D)
C34  VDC_V: 16V  ValueDisplayed: 0.1uF  [0402]  (hidden comment: GRM155R61C104KA88D)
C35  VDC_V: 25V  ValueDisplayed: 4700pF  [0402]  (hidden comment: GRM155R61E472KA01D)
C36  VDC_V: 16V  ValueDisplayed: 0.1uF  [0402]  (hidden comment: GRM155R61C104KA88D)
C37  Cap_F: 3.3nF  VDC_V: 100V  [0603]  (hidden comment: GRM188R72A332KA01D)
C38  VDC_V: 16V  ValueDisplayed: 0.1uF  [0402]  (hidden comment: GRM155R61C104KA88D)
C39  VDC_V: 16V  ValueDisplayed: 0.1uF  [0402]  (hidden comment: GRM155R61C104KA88D)
R32  ValueDisplayed: 0  [0402]  (hidden comment: CRCW04020000Z0ED)
R33  ValueDisplayed: 0  [0402]  (hidden comment: CRCW04020000Z0ED)
R34  ValueDisplayed: 499  [0402]  (hidden comment: CRCW0402499RFKED)
R35  ValueDisplayed: 0  [0402]  (hidden comment: CRCW04020000Z0ED)
R36  ValueDisplayed: 20.0k  [0402]  (hidden comment: RT0402BRD0720KL)
R37  ValueDisplayed: 499  [0402]  (hidden comment: CRCW0402499RFKED)
R38  value 100  [FP-RT0402BRD07100RL_0402-MFG]  (hidden comment: RT0402BRD07100RL)
R39  ValueDisplayed: 0  [0402]  (hidden comment: CRCW04020000Z0ED)
R40  ValueDisplayed: 0  [0402]  (hidden comment: CRCW04020000Z0ED)
R41  ValueDisplayed: 0  [0402]  (hidden comment: CRCW04020000Z0ED)
R44  ValueDisplayed: 10.0k  [0402]  (hidden comment: PCF0402-12-10K0BT1)
R45  ValueDisplayed: 20.0k  [0603]  (hidden comment: CRCW060320K0FKEA)
R46  ValueDisplayed: 40.2k  [0402]  (hidden comment: CRCW040240K2FKED)
R47  ValueDisplayed: 49.9k  [0603]  (hidden comment: CRCW060349K9FKEA)
R48  ValueDisplayed: 40.2k  [0402]  (hidden comment: CRCW040240K2FKED)
R49  ValueDisplayed: 0  [0402]  (hidden comment: CRCW04020000Z0ED)
R50  ValueDisplayed: 49.9k  [0603]  (hidden comment: CRCW060349K9FKEA)
R51  ValueDisplayed: 10.0k  [0402]  (hidden comment: PCF0402-12-10K0BT1)
R52  ValueDisplayed: 20.0k  [0603]  (hidden comment: CRCW060320K0FKEA)
U4  PartNumber: INA500BIDCKR  [DCK0006A-MFG]  (hidden comment: INA500B)
U5  INA630  [DDF0008A-MFG]
U6  INA826AIDGK  [DGK0008A_N]
U7  TLV9152IDGKR  [DGK0008A_N]  (parts A,B,C of 3)

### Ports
BATSN (in), BATSP (in), IOCP (out), IoutN (out), IoutP (out), ISENA (in), ISENB (in), LOCSEN_N (in), LOCSEN_P (in), Vbat_ACP (out), VbatN (out), VbatP (out), VoutP (out)

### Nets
5VA: C30.2 U4.6(V+)
10VA: C29.1 C34.1 C39.2 U5.8(VS+) U6.8(+VS) U7.8(V+)
-5VA: C33.1 C36.2 C38.2 U5.4(VS-) U6.5(-VS) U7.4(V-)
AGND: C28.1 C29.2 C30.1 C32.1 C33.2 C34.2 C36.1 C38.1 C39.1 R35.1 R38.1 R40.1 R45.1 R48.1 U4.2(V-) U5.5(REF) U6.6(REF)
REF1V25: R44.2 U4.5(REF)
BATSN: R39.2 U4.3(IN-) U6.1(-IN) ; port BATSN
BATSP: R32.2 U4.1(IN+) U6.4(+IN) ; port BATSP
IOCP: C35.1 R51.1 U7.1(OUT) ; port IOCP
IoutN: R40.2 R41.2 ; port IoutN
IoutP: R33.2 R36.2 R46.1 U5.7(OUT) ; port IoutP
ISENA: R37.1 ; port ISENA
ISENB: R34.1 ; port ISENB
LOCSEN_N: R50.2 ; port LOCSEN_N
LOCSEN_P: R47.2 ; port LOCSEN_P
Vbat_ACP: R49.2 ; port Vbat_ACP
VbatN: R35.2 R39.1 ; port VbatN
VbatP: R32.1 U4.4(OUT) ; port VbatP
VoutP: C37.1 R52.2 U7.7(OUT) ; port VoutP
NetC28_2: C28.2 C31.1 R33.1 R34.2 U5.3(INP)
NetC31_2: C31.2 C32.2 R37.2 R41.1 U5.2(INN)
NetC35_2: C35.2 R48.2 R51.2 U7.2(IN-)
NetC37_2: C37.2 R50.1 R52.1 U7.6(IN-)
NetR36_1: R36.1 R38.2 U5.6(FB)
NetR44_1: R44.1 R46.2 U7.3(IN+)
NetR45_2: R45.2 R47.1 U7.5(IN+)
NetR49_1: R49.1 U6.7(VOUT)

Not connected (* = marked no-connect by the designer): U5 1(NC)*; U6 2(RG)* 3(RG)*

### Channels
Sns1: designators end in _1; ports BATSN=BATSN1 BATSP=BATSP1 IOCP=IOCP1 IoutN=IoutN1 IoutP=IoutP1 ISENA=ISENA1 ISENB=ISENB1 LOCSEN_N=LOCSEN_N1 LOCSEN_P=LOCSEN_P1 Vbat_ACP=Vbat_ACP1 VbatN=VbatN1 VbatP=VbatP1 VoutP=VoutP1
Sns2: designators end in _2; ports BATSN=BATSN2 BATSP=BATSP2 IOCP=IOCP2 IoutN=IoutN2 IoutP=IoutP2 ISENA=ISENA2 ISENB=ISENB2 LOCSEN_N=LOCSEN_N2 LOCSEN_P=LOCSEN_P2 Vbat_ACP=Vbat_ACP2 VbatN=VbatN2 VbatP=VbatP2 VoutP=VoutP2
Sns3: designators end in _3; ports BATSN=BATSN3 BATSP=BATSP3 IOCP=IOCP3 IoutN=IoutN3 IoutP=IoutP3 ISENA=ISENA3 ISENB=ISENB3 LOCSEN_N=LOCSEN_N3 LOCSEN_P=LOCSEN_P3 Vbat_ACP=Vbat_ACP3 VbatN=VbatN3 VbatP=VbatP3 VoutP=VoutP3
Sns4: designators end in _4; ports BATSN=BATSN4 BATSP=BATSP4 IOCP=IOCP4 IoutN=IoutN4 IoutP=IoutP4 ISENA=ISENA4 ISENB=ISENB4 LOCSEN_N=LOCSEN_N4 LOCSEN_P=LOCSEN_P4 Vbat_ACP=Vbat_ACP4 VbatN=VbatN4 VbatP=VbatP4 VoutP=VoutP4

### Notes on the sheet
- VOLTAGE SENSE
- Current Sense
- VbatP goes to precision ADC
- BAT [0V, 5V]
- (near U5) Output current sense
- Option1: ADS932x
  Option2: INA500+ ADS8686S
- (near R41) Gain = 1+ 20k/100 =201
- Battery AC Voltage Sense
- Local Voltage Sense
- Not used because in 8v8i setup does not have external gain
- Local sense goes to C2K ADC
- Make it DNP

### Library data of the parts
C28 C32 = CMP-0006412-2: CAP, CERM, 1000 pF, 50 V, +/- 5%, C0G/NP0, 0402; Manufacturer: MuRata; TaMin_C: -55°C; Polarized: N; SizeAreaWB_mm2: 3; Value1: Unknown; U/M: EA; Value: 1000pF; TaMax_C: 125°C; SizeZ_mm: 0.6; SizeX_mm: 1; SizeY_mm: 0.5; Cap_F: 1nF; AEC Category: Q200
C29 C30 C33 C34 C36 C38 C39 = CMP-0006591-2: as C92 on sheet TIDA-010086E5_ControlCard
C31 = CMP-0007210-4: CAP, CERM, 3300 pF, 50 V, +/- 5%, C0G/NP0, 0603; Manufacturer: MuRata; TaMin_C: -55°C; Polarized: N; SizeAreaWB_mm2: 4.68; Value1: Unknown; U/M: EA; Value: 3300pF; TaMax_C: 125°C; SizeZ_mm: 1; SizeX_mm: 1.6; SizeY_mm: 0.8; SizeArea_mm2: 1.28; Cap_F: 3.3nF; AEC Category: Q200
C35 = CMP-0006611-2: CAP, CERM, 4700 pF, 25 V, +/- 10%, X5R, 0402; Manufacturer: MuRata; TaMin_C: -55°C; Polarized: N; SizeAreaWB_mm2: 3; Value1: Unknown; U/M: EA; Value: 4700pF; TaMax_C: 85°C; SizeZ_mm: 0.6; SizeX_mm: 1; SizeY_mm: 0.5; Cap_F: 4.7nF; AEC Category: Q200
C37 = CMP-0007479-4: CAP, CERM, 3300 pF, 100 V, +/- 10%, X7R, 0603; Manufacturer: MuRata; TaMin_C: -55°C; Polarized: N; SizeAreaWB_mm2: 4.68; Value1: Unknown; U/M: EA; Value: 3300pF; TaMax_C: 125°C; SizeZ_mm: 1; SizeX_mm: 1.6; SizeY_mm: 0.8; SizeArea_mm2: 1.28; AEC Category: Q200
R32 R33 R35 R39-R41 R49 = CMP-0026822-3: as R123 on sheet TIDA-010086E5_ControlCard
R34 R37 = CMP-0026402-2: RES, 499, 1%, 0.063 W, AEC-Q200 Grade 0, 0402; Manufacturer: Vishay-Dale; Power_W: 63mW; TempCo: 100 ppm/C; Value_Code: 499R; Value: 499; EIA_Code: E96; SizeX_mm: 1; SizeY_mm: 0.5; SizeZ_mm: 0.6; Value2: 0.063W; AEC Qualified: Y; VDC_V: 50V; AEC Category: Q200; AEC Grade: 0
R36 = CMP-0065358-1: RES, 20.0 k, .1%, .0625 W, 0402; Manufacturer: Yageo America; Power_W: 62.5mW; TempCo: 25 ppm/C; Value_Code: 20k0; U/M: EA; Value: 20.0k; EIA_Code: E192; Tolerance_%: 0.1%; Res_ohm: 20k; SizeX_mm: 1.0; SizeY_mm: 0.5; SizeZ_mm: 0.6; Value2: .0625W; VDC_V: 50V; AEC Category: Q200
R38 = CMP-0092050-1: Res Thin Film 0402 100 Ohm 0.1% 0.063W(1/16W) ±25ppm/C Pad SMD T/R; Manufacturer: Yageo; Power_W: 63mW; AEC Qualified: No; SizeZ_mm: 0.35mm; VDC_V: 50V; TempCo: 25ppm/°C
R44 R51 = CMP-0026796-1: RES, 10.0 k, 0.1%, 0.063 W, 0402; Manufacturer: TT Electronics/IRC; Power_W: 63mW; TempCo: 10 ppm/C; Value_Code: 10k0; Value: 10.0k; Res_ohm: 10k; SizeX_mm: 1; SizeY_mm: 0.5; SizeZ_mm: 0.6; Value2: 0.063W; AEC Qualified: N; VDC_V: 25V; AEC Category: Q200; EIA_Code: E192; U/M: EA
R45 R52 = CMP-0022204-4: RES, 20.0 k, 1%, 0.1 W, AEC-Q200 Grade 0, 0603; Manufacturer: Vishay-Dale; Power_W: 100mW; TempCo: 100 ppm/C; Value_Code: 20k0; Value: 20.0k; EIA_Code: E96; Res_ohm: 20k; SizeX_mm: 1.6; SizeY_mm: 0.8; SizeZ_mm: 1; Value2: 0.1W; SizeArea_mm2: 1.28; AEC Qualified: Y; VDC_V: 75V; AEC Category: Q200; AEC Grade: 0
R46 R48 = CMP-0026367-2: RES, 40.2 k, 1%, 0.063 W, AEC-Q200 Grade 0, 0402; Manufacturer: Vishay-Dale; Power_W: 63mW; TempCo: 100 ppm/C; Value_Code: 40k2; Value: 40.2k; EIA_Code: E96; SizeX_mm: 1; SizeY_mm: 0.5; SizeZ_mm: 0.6; Value2: 0.063W; AEC Qualified: Y; VDC_V: 50V; AEC Category: Q200; AEC Grade: 0
R47 R50 = CMP-0022447-4: as R157 on sheet TIDA-010086E5_ControlCard
U4 = CMP-0096479-1: Precision Current-Sense Amplifier Bi-Directional 1-Channel 200V/V 1.7V to 5.5V 6-Pin SC-70 T/R; Manufacturer: Texas Instruments; AEC Qualified: No; TaMax_C: +125°C; Number Of Channels: 1; Nominal Supply Current: 48uA; SizeZ_mm: 1.1mm; Standoff Height: 0mm
U5 = CMP-0121190-1: Precision, Low-Power, Indirect Current Feedback Instrumentation Amplifier; Manufacturer: Texas Instruments; SizeZ_mm: 1.1mm; AEC Qualified: No; Bandwidth: 550kHz; Input Bias Current: 0.006uA; Input Offset Voltage: 0.05mV; Max Dual Supply Voltage: 18V; Max Supply Voltage: 36V; Min Dual Supply Voltage: 2.25V; Min Supply Voltage: 4.5V; Nominal Supply Current: 300uA; Number Of Channels: 1; Output Current Per Channel: 20mA; Response Time: 25us; Standoff Height: 0mm; TaMax_C: +125°C; TaMin_C: -40°C; TJmax_C: +175°C; Voltage Gain: 0.02-1V/mV
U6 = CMP-0038162-3: Precision, 200-μA Supply Current, 36-V Supply Instrumentation Amplifier, DGK0008A (VSSOP-8); Manufacturer: Texas Instruments; CMRR(Min)(dB): 84; Noise at 1kHz(Typ)(nV/rt(Hz)): 18; Non-Linearity (+/-)(Max)(%): 0.0005; Vs(Min)(V): 2.7; Input Offset Drift (+/-)(Max)(uV/Degrees Celsius): 2; Quiescent Current (+/-)(Typ)(mA): 0.2; Input Bias Current (+/-)(Max)(nA): 65; Vs(Max)(V): 36; Output Offset Drift (+/-)(Max)(uV/Degrees Celsius): 10; Input Offset (+/-)(Max)(uV): 150; Gain(V/V): 1 to 1000; Eco-Plan: Green (RoHS & no Sb/Br); Number of Channels: 1; Output Offset (+/-)(Max)(uV): 700; AEC Category: Q200; AEC Qualified: N; CompType: IC; SizeAreaWB_mm2: 23.6; SizeArea_mm2: 14.7; SizeX_mm: 4.9; SizeY_mm: 3; SizeZ_mm: 1.1; Rating: Catalog
U7 = CMP-0100002-2: as U21 on sheet TIDA-010086E5_ControlCard

## Sheet TIDA-010086E5_ADC.SchDoc
size C; Date: Not shown in title block; ApprovedBy: Not shown in title block; CheckedBy: Not shown in title block; Author: Not shown in title block; CompanyName: Not shown in title block; DrawnBy: Battery test; Engineer: Not shown in title block; Organization: Not shown in title block; Address1: Not shown in title block; Address2: Not shown in title block; Address3: Not shown in title block; Address4: Not shown in title block; DocumentNumber: 5; Revision: Use project parameter SCH_Rev; SheetNumber: 5; SheetTotal: 8; PageSetup: Record=PageOptions¦CenterHorizontal=True¦CenterVertical=True¦PrintScale=1.00¦XCorrection=1.00¦YCorrection=1.00¦PrintKind=0¦BorderSize=5000000¦LeftOffset=0¦BottomOffset=0¦Orientation=2¦PaperLength=1000¦PaperWidth=1000¦Scale=100¦PaperSource=15¦PrintQuality=600¦MediaType=1¦DitherType=10¦PaperKind=Letter¦PrintScaleMode=1
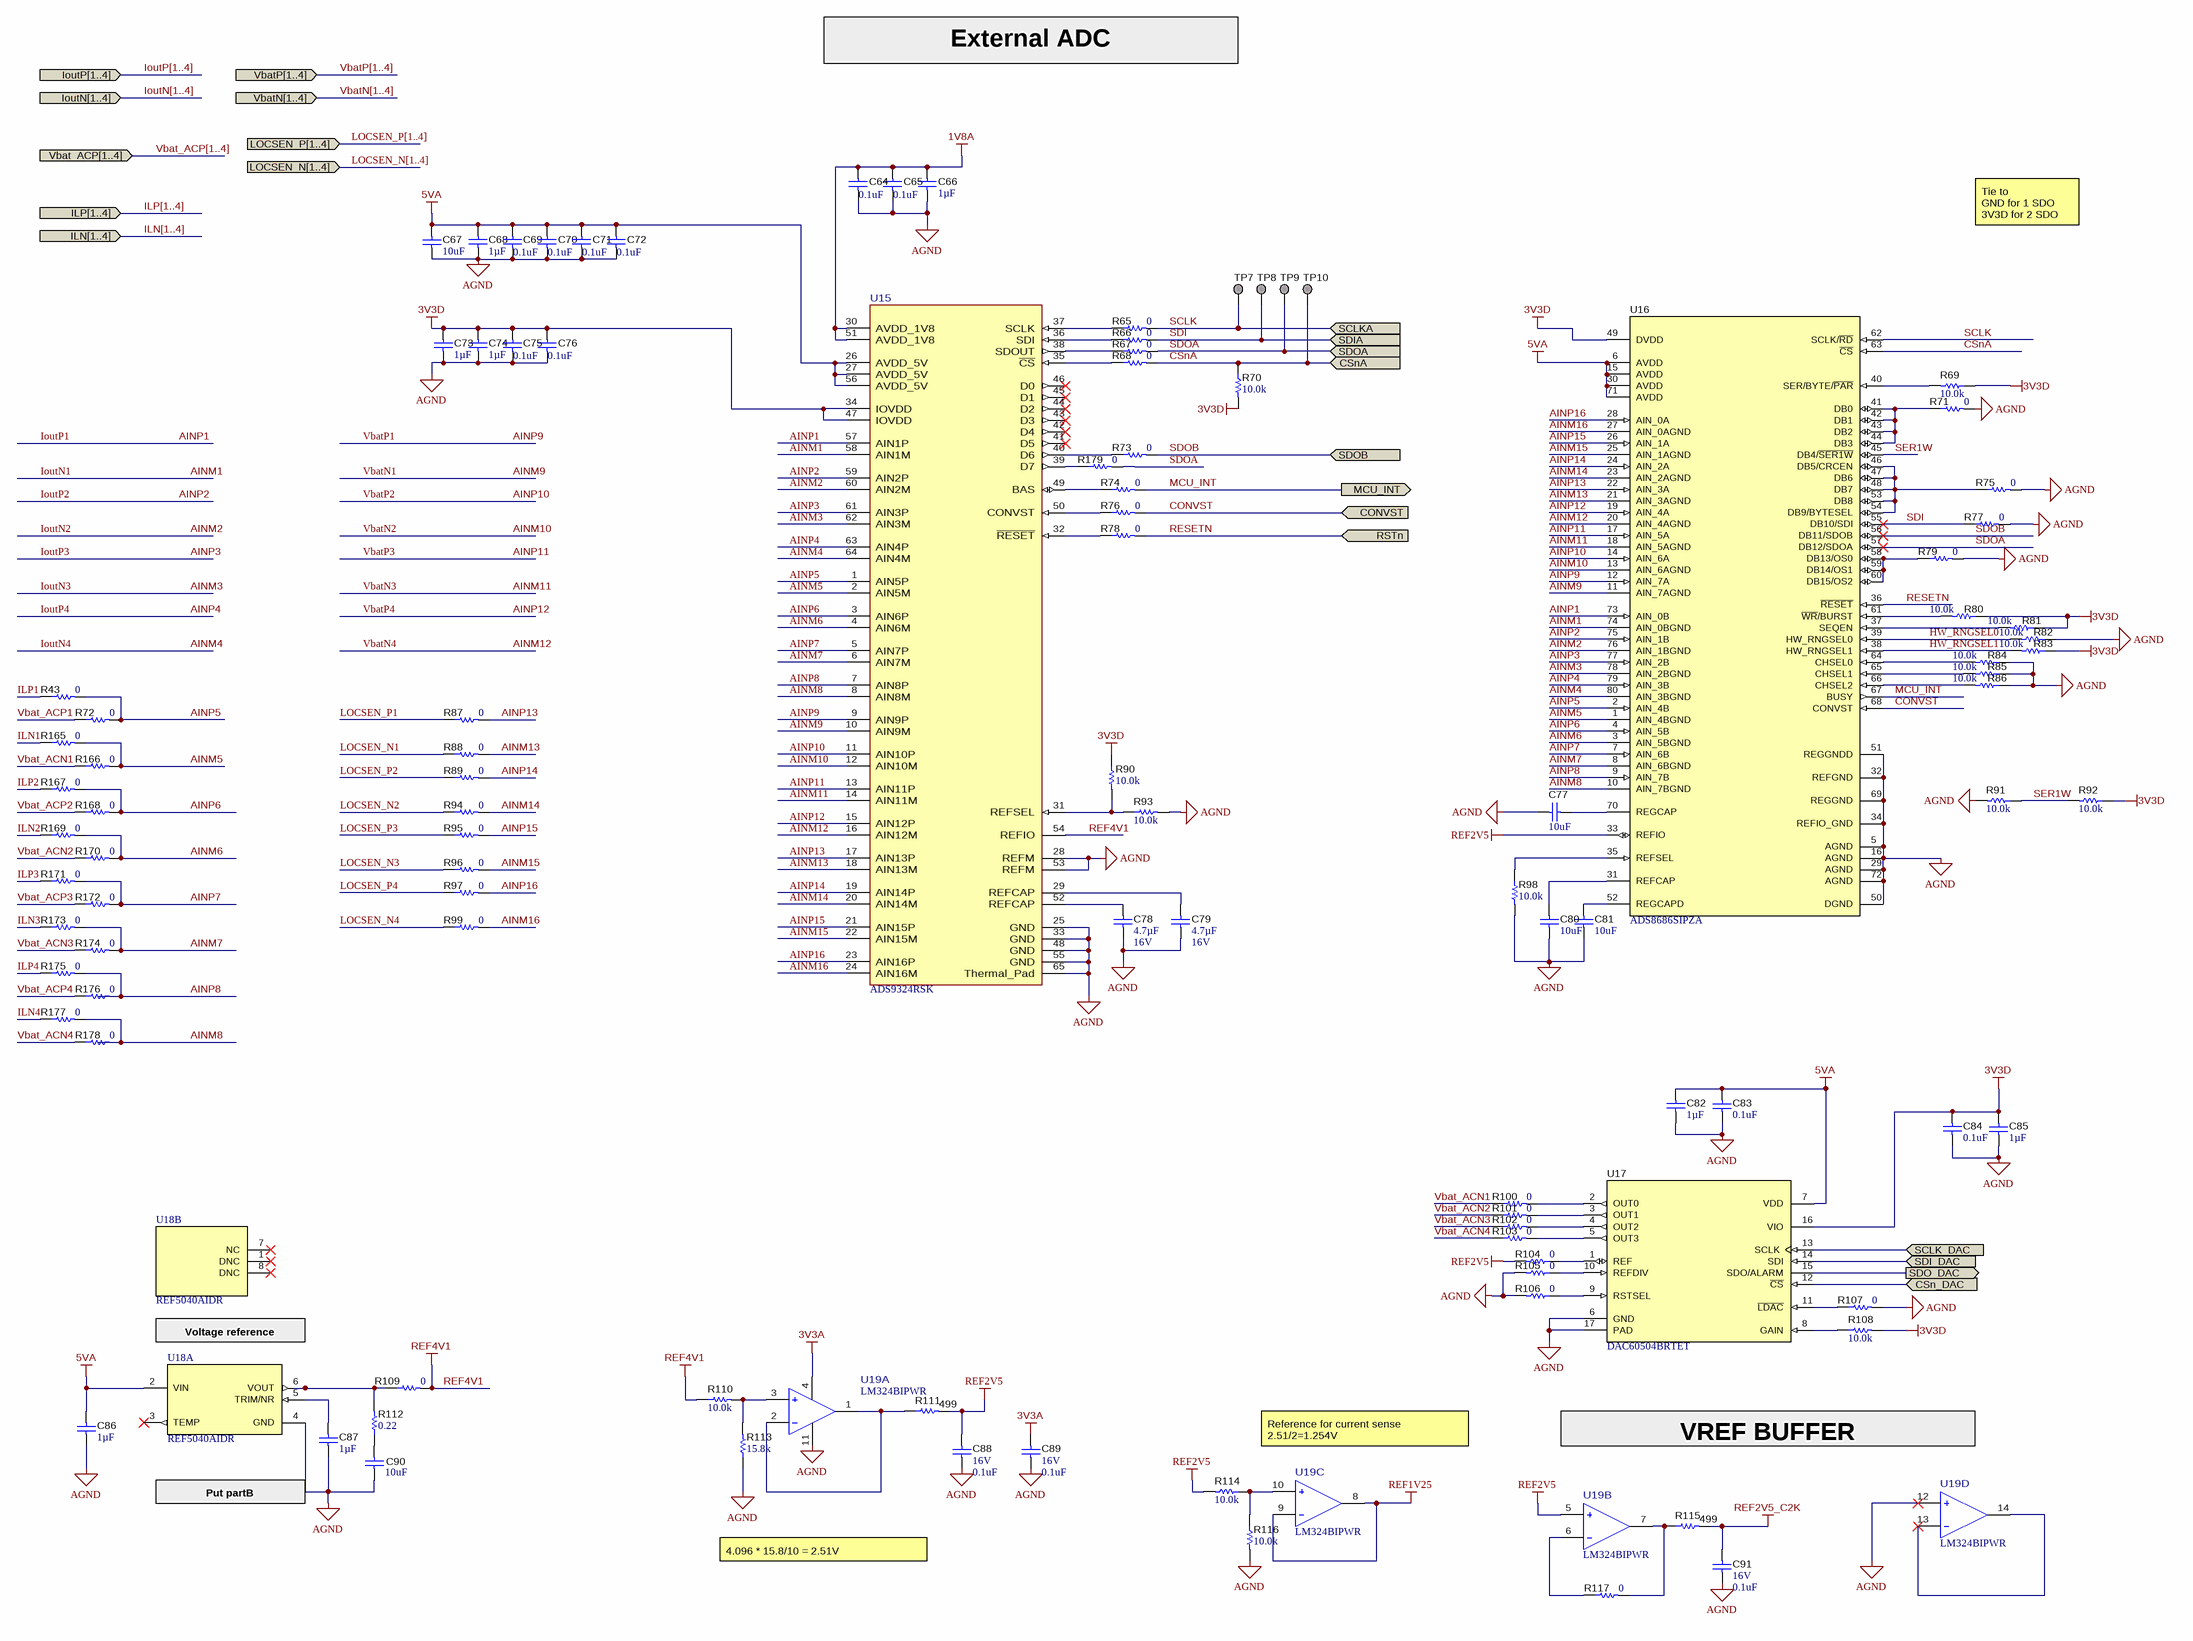
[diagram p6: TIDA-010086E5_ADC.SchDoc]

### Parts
C64  ValueDisplayed: 0.1uF  [0402S]  (hidden comment: GRM155R61C104KA88D)
C65  ValueDisplayed: 0.1uF  [0402S]  (hidden comment: GRM155R61C104KA88D)
C66  ValueDisplayed: 1µF  [0603S]  (hidden comment: CGA3E1X7R1E105K080AC)
C67  ValueDisplayed: 10uF  [0603]  (hidden comment: GRM188R61E106MA73D)
C68  ValueDisplayed: 1µF  [0603S]  (hidden comment: CGA3E1X7R1E105K080AC)
C69  ValueDisplayed: 0.1uF  [0402S]  (hidden comment: GRM155R61C104KA88D)
C70  ValueDisplayed: 0.1uF  [0402S]  (hidden comment: GRM155R61C104KA88D)
C71  ValueDisplayed: 0.1uF  [0402S]  (hidden comment: GRM155R61C104KA88D)
C72  ValueDisplayed: 0.1uF  [0402S]  (hidden comment: GRM155R61C104KA88D)
C73  ValueDisplayed: 1µF  [0603S]  (hidden comment: CGA3E1X7R1E105K080AC)
C74  ValueDisplayed: 1µF  [0603S]  (hidden comment: CGA3E1X7R1E105K080AC)
C75  ValueDisplayed: 0.1uF  [0402S]  (hidden comment: GRM155R61C104KA88D)
C76  ValueDisplayed: 0.1uF  [0402S]  (hidden comment: GRM155R61C104KA88D)
C77  ValueDisplayed: 10uF  [0603]  (hidden comment: GRM188R61E106MA73D)
C78  Cap_F: 4.7µF  VDC_V: 16V  [0603]  (hidden comment: GRM188Z71C475KE21D)
C79  Cap_F: 4.7µF  VDC_V: 16V  [0603]  (hidden comment: GRM188Z71C475KE21D)
C80  ValueDisplayed: 10uF  [0603]  (hidden comment: GRM188R61E106MA73D)
C81  ValueDisplayed: 10uF  [0603]  (hidden comment: GRM188R61E106MA73D)
C82  ValueDisplayed: 1µF  [0603S]  (hidden comment: CGA3E1X7R1E105K080AC)
C83  ValueDisplayed: 0.1uF  [0402S]  (hidden comment: GRM155R61C104KA88D)
C84  ValueDisplayed: 0.1uF  [0402S]  (hidden comment: GRM155R61C104KA88D)
C85  ValueDisplayed: 1µF  [0603S]  (hidden comment: CGA3E1X7R1E105K080AC)
C86  ValueDisplayed: 1µF  [0603S]  (hidden comment: CGA3E1X7R1E105K080AC)
C87  ValueDisplayed: 1µF  [0603S]  (hidden comment: CGA3E1X7R1E105K080AC)
C88  VDC_V: 16V  ValueDisplayed: 0.1uF  [0402]  (hidden comment: GRM155R71C104JA88D)
C89  VDC_V: 16V  ValueDisplayed: 0.1uF  [0402S]  (hidden comment: GRM155R61C104KA88D)
C90  ValueDisplayed: 10uF  [0603]  (hidden comment: GRM188R61E106MA73D)
C91  VDC_V: 16V  ValueDisplayed: 0.1uF  [0402]  (hidden comment: GRM155R71C104JA88D)
R43  ValueDisplayed: 0  [0402S]  (hidden comment: CRCW04020000Z0ED)
R65  ValueDisplayed: 0  [0402S]  (hidden comment: CRCW04020000Z0ED)
R66  ValueDisplayed: 0  [0402S]  (hidden comment: CRCW04020000Z0ED)
R67  ValueDisplayed: 0  [0402S]  (hidden comment: CRCW04020000Z0ED)
R68  ValueDisplayed: 0  [0402S]  (hidden comment: CRCW04020000Z0ED)
R69  ValueDisplayed: 10.0k  [0603]  (hidden comment: CRCW060310K0FKEA)
R70  ValueDisplayed: 10.0k  [0603]  (hidden comment: CRCW060310K0FKEA)
R71  ValueDisplayed: 0  [0402S]  (hidden comment: CRCW04020000Z0ED)
R72  ValueDisplayed: 0  [0402S]  (hidden comment: CRCW04020000Z0ED)
R73  ValueDisplayed: 0  [0402S]  (hidden comment: CRCW04020000Z0ED)
R74  ValueDisplayed: 0  [0402S]  (hidden comment: CRCW04020000Z0ED)
R75  ValueDisplayed: 0  [0402S]  (hidden comment: CRCW04020000Z0ED)
R76  ValueDisplayed: 0  [0402S]  (hidden comment: CRCW04020000Z0ED)
R77  ValueDisplayed: 0  [0402S]  (hidden comment: CRCW04020000Z0ED)
R78  ValueDisplayed: 0  [0402S]  (hidden comment: CRCW04020000Z0ED)
R79  ValueDisplayed: 0  [0402S]  (hidden comment: CRCW04020000Z0ED)
R80  ValueDisplayed: 10.0k  [0603]  (hidden comment: CRCW060310K0FKEA)
R81  ValueDisplayed: 10.0k  [0603]  (hidden comment: CRCW060310K0FKEA)
R82  ValueDisplayed: 10.0k  [0603]  (hidden comment: CRCW060310K0FKEA)
R83  ValueDisplayed: 10.0k  [0603]  (hidden comment: CRCW060310K0FKEA)
R84  ValueDisplayed: 10.0k  [0603]  (hidden comment: CRCW060310K0FKEA)
R85  ValueDisplayed: 10.0k  [0603]  (hidden comment: CRCW060310K0FKEA)
R86  ValueDisplayed: 10.0k  [0603]  (hidden comment: CRCW060310K0FKEA)
R87  ValueDisplayed: 0  [0402S]  (hidden comment: CRCW04020000Z0ED)
R88  ValueDisplayed: 0  [0402S]  (hidden comment: CRCW04020000Z0ED)
R89  ValueDisplayed: 0  [0402S]  (hidden comment: CRCW04020000Z0ED)
R90  ValueDisplayed: 10.0k  [0603]  (hidden comment: CRCW060310K0FKEA)
R91  ValueDisplayed: 10.0k  [0603]  (hidden comment: CRCW060310K0FKEA)
R92  ValueDisplayed: 10.0k  [0603]  (hidden comment: CRCW060310K0FKEA)
R93  ValueDisplayed: 10.0k  [0603]  (hidden comment: CRCW060310K0FKEA)
R94  ValueDisplayed: 0  [0402S]  (hidden comment: CRCW04020000Z0ED)
R95  ValueDisplayed: 0  [0402S]  (hidden comment: CRCW04020000Z0ED)
R96  ValueDisplayed: 0  [0402S]  (hidden comment: CRCW04020000Z0ED)
R97  ValueDisplayed: 0  [0402S]  (hidden comment: CRCW04020000Z0ED)
R98  ValueDisplayed: 10.0k  [0603]  (hidden comment: CRCW060310K0FKEA)
R99  ValueDisplayed: 0  [0402S]  (hidden comment: CRCW04020000Z0ED)
R100  ValueDisplayed: 0  [0402S]  (hidden comment: CRCW04020000Z0ED)
R101  ValueDisplayed: 0  [0402S]  (hidden comment: CRCW04020000Z0ED)
R102  ValueDisplayed: 0  [0402S]  (hidden comment: CRCW04020000Z0ED)
R103  ValueDisplayed: 0  [0402S]  (hidden comment: CRCW04020000Z0ED)
R104  ValueDisplayed: 0  [0402S]  (hidden comment: CRCW04020000Z0ED)
R105  ValueDisplayed: 0  [0402S]  (hidden comment: CRCW04020000Z0ED)
R106  ValueDisplayed: 0  [0402S]  (hidden comment: CRCW04020000Z0ED)
R107  ValueDisplayed: 0  [0402S]  (hidden comment: CRCW04020000Z0ED)
R108  ValueDisplayed: 10.0k  [0603]  (hidden comment: CRCW060310K0FKEA)
R109  ValueDisplayed: 0  [0402S]  (hidden comment: CRCW04020000Z0ED)
R110  ValueDisplayed: 10.0k  [0603]  (hidden comment: CRCW060310K0FKEA)
R111  ValueDisplayed: 499  [0402]  (hidden comment: CRCW0402499RFKED)
R112  ValueDisplayed: 0.22  [0402]  (hidden comment: ERJ-2BQFR22X)
R113  ValueDisplayed: 15.8k  [0603]  (hidden comment: CRCW060315K8FKEA)
R114  ValueDisplayed: 10.0k  [0603]  (hidden comment: CRCW060310K0FKEA)
R115  ValueDisplayed: 499  [0402]  (hidden comment: CRCW0402499RFKED)
R116  ValueDisplayed: 10.0k  [0603]  (hidden comment: CRCW060310K0FKEA)
R117  ValueDisplayed: 0  [0402S]  (hidden comment: CRCW04020000Z0ED)
R165  ValueDisplayed: 0  [0402S]  (hidden comment: CRCW04020000Z0ED)
R166  ValueDisplayed: 0  [0402S]  (hidden comment: CRCW04020000Z0ED)
R167  ValueDisplayed: 0  [0402S]  (hidden comment: CRCW04020000Z0ED)
R168  ValueDisplayed: 0  [0402S]  (hidden comment: CRCW04020000Z0ED)
R169  ValueDisplayed: 0  [0402S]  (hidden comment: CRCW04020000Z0ED)
R170  ValueDisplayed: 0  [0402S]  (hidden comment: CRCW04020000Z0ED)
R171  ValueDisplayed: 0  [0402S]  (hidden comment: CRCW04020000Z0ED)
R172  ValueDisplayed: 0  [0402S]  (hidden comment: CRCW04020000Z0ED)
R173  ValueDisplayed: 0  [0402S]  (hidden comment: CRCW04020000Z0ED)
R174  ValueDisplayed: 0  [0402S]  (hidden comment: CRCW04020000Z0ED)
R175  ValueDisplayed: 0  [0402S]  (hidden comment: CRCW04020000Z0ED)
R176  ValueDisplayed: 0  [0402S]  (hidden comment: CRCW04020000Z0ED)
R177  ValueDisplayed: 0  [0402S]  (hidden comment: CRCW04020000Z0ED)
R178  ValueDisplayed: 0  [0402S]  (hidden comment: CRCW04020000Z0ED)
R179  ValueDisplayed: 0  [0402S]  (hidden comment: CRCW04020000Z0ED)
TP7  TP_SM_1MM  [TP_SM_1MM]  (value not drawn)  (no BOM)
TP8  TP_SM_1MM  [TP_SM_1MM]  (value not drawn)  (no BOM)
TP9  TP_SM_1MM  [TP_SM_1MM]  (value not drawn)  (no BOM)
TP10  TP_SM_1MM  [TP_SM_1MM]  (value not drawn)  (no BOM)
U15  ADS9324RSK  [RSK0064B-MFG]
U16  ADS8686SIPZA  [PZA0080A_N]
U17  DAC60504BRTET  [RTE0016D]
U18  REF5040AIDR  [D0008A_N]  (parts A,B of 2)
U19  LM324BIPWR  [PW0014A-MFG]  (parts A,B,C,D of 4)

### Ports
CONVST (in), CSn_DAC (in), CSnA (in), ILN[1..4] (in), ILP[1..4] (in), IoutN[1..4] (in), IoutP[1..4] (in), LOCSEN_N[1..4] (in), LOCSEN_P[1..4] (in), MCU_INT (out), RSTn (in), SCLK_DAC (in), SCLKA (in), SDI_DAC (in), SDIA (in), SDO_DAC (out), SDOA (in), SDOB (in), Vbat_ACP[1..4] (in), VbatN[1..4] (in), VbatP[1..4] (in)

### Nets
1V8A: C64.2 C65.2 C66.2 U15.30(AVDD_1V8) U15.51(AVDD_1V8)
3V3A: C89.1 U19.4(VCC+)
3V3D: C73.2 C74.2 C75.2 C76.2 C84.1 C85.2 R69.1 R70.2 R80.1 R81.1 R83.1 R90.1 R92.1 R108.2 U15.34(IOVDD) U15.47(IOVDD) U16.49(DVDD) U17.16(VIO)
5VA: C67.1 C68.2 C69.2 C70.2 C71.2 C72.2 C82.2 C83.1 C86.1 U15.26(AVDD_5V) U15.27(AVDD_5V) U15.56(AVDD_5V) U16.6(AVDD) U16.15(AVDD) U16.30(AVDD) U16.71(AVDD) U17.7(VDD) U18.2(VIN)
AGND: C64.1 C65.1 C66.1 C67.2 C68.1 C69.1 C70.1 C71.1 C72.1 C73.1 C74.1 C75.1 C76.1 C77.1 C78.2 C79.2 C80.2 C81.2 C82.1 C83.2 C84.2 C85.1 C86.2 C87.2 C88.2 C89.2 C90.2 C91.2 R71.2 R75.2 R77.2 R79.2 R82.1 R84.1 R85.1 R86.1 R91.2 R93.2 R98.2 R105.2 R106.2 R107.2 R113.1 R116.2 U15.25(GND) U15.28(REFM) U15.33(GND) U15.48(GND) U15.53(REFM) U15.55(GND) U15.65(Thermal_Pad) U16.5(AGND) U16.16(AGND) U16.29(AGND) U16.32(REFGND) U16.34(REFIO_GND) U16.50(DGND) U16.51(REGGNDD) U16.69(REGGND) U16.72(AGND) U17.6(GND) U17.17(PAD) U18.4(GND) U19.11(VCC-) U19.12(4IN+)
REF1V25: U19.8(3OUT) U19.9(3IN-)
REF2V5: C88.1 R104.2 R111.2 R114.2 U16.33(REFIO) U19.5(2IN+)
REF2V5_C2K: C91.1 R115.2
REF4V1: R109.2 R110.1 U15.54(REFIO)
AINM5: R165.2 R166.2 U15.2(AIN5M) U16.1(AIN_4BGND)
AINM6: R169.2 R170.2 U15.4(AIN6M) U16.3(AIN_5BGND)
AINM7: R173.2 R174.2 U15.6(AIN7M) U16.8(AIN_6BGND)
AINM8: R177.2 R178.2 U15.8(AIN8M) U16.10(AIN_7BGND)
AINM13: R88.2 U15.18(AIN13M) U16.21(AIN_3AGND)
AINM14: R94.2 U15.20(AIN14M) U16.23(AIN_2AGND)
AINM15: R96.2 U15.22(AIN15M) U16.25(AIN_1AGND)
AINM16: R99.2 U15.24(AIN16M) U16.27(AIN_0AGND)
AINP5: R43.2 R72.2 U15.1(AIN5P) U16.2(AIN_4B)
AINP6: R167.2 R168.2 U15.3(AIN6P) U16.4(AIN_5B)
AINP7: R171.2 R172.2 U15.5(AIN7P) U16.7(AIN_6B)
AINP8: R175.2 R176.2 U15.7(AIN8P) U16.9(AIN_7B)
AINP13: R87.2 U15.17(AIN13P) U16.22(AIN_3A)
AINP14: R89.2 U15.19(AIN14P) U16.24(AIN_2A)
AINP15: R95.2 U15.21(AIN15P) U16.26(AIN_1A)
AINP16: R97.2 U15.23(AIN16P) U16.28(AIN_0A)
CONVST: R76.2 U16.68(CONVST) ; port CONVST
CSn_DAC: U17.12(~{CS}) ; port CSn_DAC
CSnA: R68.2 R70.1 TP10.1 U16.63(~{CS}) ; port CSnA
HW_RNGSEL0: R82.2 U16.39(HW_RNGSEL0)
HW_RNGSEL1: R83.2 U16.38(HW_RNGSEL1)
ILN1: R165.1
ILN2: R169.1
ILN3: R173.1
ILN4: R177.1
ILP1: R43.1
ILP2: R167.1
ILP3: R171.1
ILP4: R175.1
IoutN1: U15.58(AIN1M) U16.74(AIN_0BGND)  [also labelled AINM1]
IoutN2: U15.60(AIN2M) U16.76(AIN_1BGND)  [also labelled AINM2]
IoutN3: U15.62(AIN3M) U16.78(AIN_2BGND)  [also labelled AINM3]
IoutN4: U15.64(AIN4M) U16.80(AIN_3BGND)  [also labelled AINM4]
IoutP1: U15.57(AIN1P) U16.73(AIN_0B)  [also labelled AINP1]
IoutP2: U15.59(AIN2P) U16.75(AIN_1B)  [also labelled AINP2]
IoutP3: U15.61(AIN3P) U16.77(AIN_2B)  [also labelled AINP3]
IoutP4: U15.63(AIN4P) U16.79(AIN_3B)  [also labelled AINP4]
LOCSEN_N1: R88.1
LOCSEN_N2: R94.1
LOCSEN_N3: R96.1
LOCSEN_N4: R99.1
LOCSEN_P1: R87.1
LOCSEN_P2: R89.1
LOCSEN_P3: R95.1
LOCSEN_P4: R97.1
MCU_INT: R74.2 U16.67(BUSY) ; port MCU_INT
RESETN: R78.2 U16.36(~{RESET}) ; port RSTn  [project net RSTn]
SCLK: R65.2 TP7.1 U16.62(SCLK/~{RD}) ; port SCLKA  [project net SCLKA]
SCLK_DAC: U17.13(SCLK) ; port SCLK_DAC
SDI: R66.2 R77.1 TP8.1 U16.55(DB10/SDI) ; port SDIA  [project net SDIA]
SDI_DAC: U17.14(SDI) ; port SDI_DAC
SDO_DAC: U17.15(SDO/ALARM) ; port SDO_DAC
SDOA: R67.2 R179.2 TP9.1 U16.57(DB12/SDOA) ; port SDOA
SDOB: R73.2 U16.56(DB11/SDOB) ; port SDOB
SER1W: R91.1 R92.2 U16.45(DB4/~{SER1W})
Vbat_ACN1: R100.1 R166.1
Vbat_ACN2: R101.1 R170.1
Vbat_ACN3: R102.1 R174.1
Vbat_ACN4: R103.1 R178.1
Vbat_ACP1: R72.1
Vbat_ACP2: R168.1
Vbat_ACP3: R172.1
Vbat_ACP4: R176.1
VbatN1: U15.10(AIN9M) U16.11(AIN_7AGND)  [also labelled AINM9]
VbatN2: U15.12(AIN10M) U16.13(AIN_6AGND)  [also labelled AINM10]
VbatN3: U15.14(AIN11M) U16.18(AIN_5AGND)  [also labelled AINM11]
VbatN4: U15.16(AIN12M) U16.20(AIN_4AGND)  [also labelled AINM12]
VbatP1: U15.9(AIN9P) U16.12(AIN_7A)  [also labelled AINP9]
VbatP2: U15.11(AIN10P) U16.14(AIN_6A)  [also labelled AINP10]
VbatP3: U15.13(AIN11P) U16.17(AIN_5A)  [also labelled AINP11]
VbatP4: U15.15(AIN12P) U16.19(AIN_4A)  [also labelled AINP12]
NetC77_2: C77.2 U16.70(REGCAP)
NetC78_1: C78.1 U15.52(REFCAP)
NetC79_1: C79.1 U15.29(REFCAP)
NetC80_1: C80.1 U16.31(REFCAP)
NetC81_1: C81.1 U16.52(REGCAPD)
NetC87_1: C87.1 U18.5(TRIM/NR)
NetC90_1: C90.1 R112.1
NetR65_1: R65.1 U15.37(SCLK)
NetR66_1: R66.1 U15.36(SDI)
NetR67_1: R67.1 U15.38(SDOUT)
NetR68_1: R68.1 U15.35(~{CS})
NetR69_2: R69.2 U16.40(SER/BYTE/~{PAR})
NetR71_1: R71.1 U16.41(DB0) U16.42(DB1) U16.43(DB2) U16.44(DB3)
NetR73_1: R73.1 U15.40(D6)
NetR74_1: R74.1 U15.49(BAS)
NetR75_1: R75.1 U16.46(DB5/CRCEN) U16.47(DB6) U16.48(DB7) U16.53(DB8) U16.54(DB9/BYTESEL)
NetR76_1: R76.1 U15.50(CONVST)
NetR78_1: R78.1 U15.32(~{RESET})
NetR79_1: R79.1 U16.58(DB13/OS0) U16.59(DB14/OS1) U16.60(DB15/OS2)
NetR80_2: R80.2 U16.61(~{WR}/BURST)
NetR81_2: R81.2 U16.37(SEQEN)
NetR84_2: R84.2 U16.64(CHSEL0)
NetR85_2: R85.2 U16.65(CHSEL1)
NetR86_2: R86.2 U16.66(CHSEL2)
NetR90_2: R90.2 R93.1 U15.31(REFSEL)
NetR98_1: R98.1 U16.35(REFSEL)
NetR100_2: R100.2 U17.2(OUT0)
NetR101_2: R101.2 U17.3(OUT1)
NetR102_2: R102.2 U17.4(OUT2)
NetR103_2: R103.2 U17.5(OUT3)
NetR104_1: R104.1 U17.1(REF)
NetR105_1: R105.1 U17.10(REFDIV)
NetR106_1: R106.1 U17.9(RSTSEL)
NetR107_1: R107.1 U17.11(~{LDAC})
NetR108_1: R108.1 U17.8(GAIN)
NetR109_1: R109.1 R112.2 U18.6(VOUT)
NetR110_2: R110.2 R113.2 U19.3(1IN+)
NetR111_1: R111.1 U19.1(1OUT) U19.2(1IN-)
NetR114_1: R114.1 R116.1 U19.10(3IN+)
NetR115_1: R115.1 R117.2 U19.7(2OUT)
NetR117_1: R117.1 U19.6(2IN-)
NetR179_1: R179.1 U15.39(D7)
NetU19_13: U19.13(4IN-) U19.14(4OUT)

Not connected (* = marked no-connect by the designer): U15 41(D5)* 42(D4)* 43(D3)* 44(D2)* 45(D1)* 46(D0)*; U18 1(DNC)* 3(TEMP)* 7(NC)* 8(DNC)*

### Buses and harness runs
bus ILN[1..4] = port ILN[1..4]
bus ILP[1..4] = port ILP[1..4]
bus IoutN[1..4] = port IoutN[1..4]
bus IoutP[1..4] = port IoutP[1..4]
bus LOCSEN_N[1..4] = port LOCSEN_N[1..4]
bus LOCSEN_P[1..4] = port LOCSEN_P[1..4]
bus Vbat_ACP[1..4] = port Vbat_ACP[1..4]
bus VbatN[1..4] = port VbatN[1..4]
bus VbatP[1..4] = port VbatP[1..4]

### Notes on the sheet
- External ADC
- Tie to
  GND for 1 SDO
  3V3D for 2 SDO
- Voltage reference
- Reference for current sense
  2.51/2=1.254V
- VREF BUFFER
- Put partB
- 4.096 * 15.8/10 = 2.51V

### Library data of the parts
C64 C65 C69-C72 C75 C76 C83 C84 = CMP-0006591-2: CAP, CERM, 0.1 uF, 16 V, +/- 10%, X5R, 0402; Manufacturer: MuRata; TaMin_C: -55°C; Polarized: N; SizeAreaWB_mm2: 3; Value1: Unknown; U/M: EA; Value: 0.1uF; TaMax_C: 85°C; SizeZ_mm: 0.6; SizeX_mm: 1; SizeY_mm: 0.5; Cap_Case: 0402; Value2: 16V; Cap_F: 100nF; AEC Category: Q200
C66 C68 C73 C74 C82 C85-C87 = CMP-0076705-3: CAP, CERM, 1 µF, 25 V,+/- 10%, X7R, AEC-Q200 Grade 1, 0603; Manufacturer: TDK; Polarized: N; Value: 1uF; U/M: EA; VDC_V: 25V; TaMin_C: -55°C; TaMax_C: 125°C; Cap_Case: 1.6x0.8x0.8mm; SizeAreaWB_mm2: 4.68; SizeArea_mm2: 1.28; AEC Qualified: Y; AEC Category: Q200; SizeZ_mm: 1.0; AEC Grade: 1; SizeY_mm: 0.8; SizeX_mm: 1.6
C67 C77 C80 C81 C90 = CMP-0007344-5: CAP, CERM, 10 uF, 25 V, +/- 20%, X5R, 0603; Manufacturer: MuRata; Polarized: N; Value: 10uF; U/M: EA; Cap_F: 10µF; Value1: Unknown; VDC_V: 25V; TaMin_C: -55°C; TaMax_C: 85°C; SizeArea_mm2: 1.28; SizeAreaWB_mm2: 4.68; SizeX_mm: 1.6; SizeY_mm: 0.8; SizeZ_mm: 1; AEC Category: Q200
C78 C79 = CMP-0064936-4: CAP, CERM, 4.7 uF, 16 V,+/- 10%, X7R, 0603; Manufacturer: MuRata; TaMin_C: -55°C; Polarized: N; SizeAreaWB_mm2: 4.68; Value1: Unknown; U/M: EA; Value: 4.7uF; TaMax_C: 125°C; SizeZ_mm: 1; SizeX_mm: 1.6; SizeY_mm: 0.8; SizeArea_mm2: 1.28; AEC Category: Q200
C88 C91 = CMP-0006640-1: CAP, CERM, 0.1 uF, 16 V, +/- 5%, X7R, 0402; Manufacturer: MuRata; TaMin_C: -55°C; Polarized: N; SizeAreaWB_mm2: 3; Value1: Unknown; U/M: EA; Value: 0.1uF; TaMax_C: 125°C; SizeZ_mm: 0.6; SizeX_mm: 1; SizeY_mm: 0.5; Cap_F: 100nF; AEC Category: Q200
C89 = CMP-0006591-2: CAP, CERM, 0.1 uF, 16 V, +/- 10%, X5R, 0402; Manufacturer: MuRata; TaMin_C: -55°C; Polarized: N; SizeAreaWB_mm2: 3; Value1: Unknown; U/M: EA; Value: 0.1uF; TaMax_C: 85°C; SizeZ_mm: 0.6; SizeX_mm: 1; SizeY_mm: 0.5; Cap_Case: 0402; Cap_F: 100nF; AEC Category: Q200
R43 R65-R68 R71-R79 R87-R89 R94-R97 R99-R107 R109 R117 R165-R179 = CMP-0026822-3: as R123 on sheet TIDA-010086E5_ControlCard
R69 R70 R80-R86 R90-R93 R98 R108 R110 R114 R116 = CMP-0021998-4: RES, 10.0 k, 1%, 0.1 W, AEC-Q200 Grade 0, 0603; Manufacturer: Vishay-Dale; Power_W: 100mW; TempCo: 100 ppm/C; Value_Code: 10k0; Value: 10.0k; EIA_Code: E96; Res_ohm: 10k; SizeX_mm: 1.6; SizeY_mm: 0.8; SizeZ_mm: 1; Value2: 0.1W; SizeArea_mm2: 1.28; AEC Qualified: Y; VDC_V: 75V; AEC Category: Q200; AEC Grade: 0
R111 R115 = CMP-0026402-2: as R34 on sheet TIDA-010086E5_V_I_Sense
R112 = CMP-0026632-2: RES, 0.22, 1%, 0.125 W, AEC-Q200 Grade 0, 0402; Manufacturer: Panasonic; Power_W: 125mW; TempCo: 250 ppm/C; Value_Code: R220; Value: 0.22; EIA_Code: E96; SizeX_mm: 1; SizeY_mm: 0.5; SizeZ_mm: 0.6; Value2: 0.125W; AEC Qualified: Y; AEC Category: Q200; AEC Grade: 0; SizeAreaWB_mm2: 3
R113 = CMP-0022068-4: RES, 15.8 k, 1%, 0.1 W, AEC-Q200 Grade 0, 0603; Manufacturer: Vishay-Dale; Power_W: 100mW; TempCo: 100 ppm/C; Value_Code: 15k8; Value: 15.8k; EIA_Code: E96; SizeX_mm: 1.6; SizeY_mm: 0.8; SizeZ_mm: 1; Value2: 0.1W; SizeArea_mm2: 1.28; AEC Qualified: Y; VDC_V: 75V; AEC Category: Q200; AEC Grade: 0
TP7-TP10 = CMP-0003825-1: 1mm Test Point, SMT; Manufacturer: Any
U15 = CMP-0124125-1: 16-Channel, 16-Bit, 1-MSPS Simultaneous-Sampling SAR ADC with Bipolar Inputs on a Single Supply; Manufacturer: Texas Instruments; SizeZ_mm: 1mm; AEC Qualified: No; Data Polarity: Single Ended/Differential; Interface: SPI; Max Supply Voltage: 5.25V; Min Supply Voltage: 1.75V; Number Of Channels: 16; Resolution: 16bits; Sampling Rate: 1Msps; Standoff Height: 0mm; TaMax_C: +125°C; TaMin_C: -40°C; TJmax_C: +150°C
U16 = CMP-0860945-1: 16-Channel, 16-Bit, 1-MSPS, Dual, Simultaneous Sampling ADC With Integrated Analog Front End, PZA0080A (LQFP-80); Manufacturer: Texas Instruments; SizeAreaWB_mm2: 324; SizeY_mm: 16; SizeZ_mm: 1.6; SizeArea_mm2: 256; AEC Category: Q200; CompType: IC; AEC Qualified: N
U17 = CMP-0078298-1: Quad, 14-Bit, SPI Voltage Output DAC With Internal Reference, RTE0016D (WQFN-16); Alternate Manufacturer: Texas Instruments; SizeAreaWB_mm2: 16; SizeZ_mm: 0.8; SizeX_mm: 3; SizeArea_mm2: 9; CompType: IC; AEC Qualified: N; AEC Category: Q200
U18 = CMP-0032601-1: Low Noise, Very Low Drift, Precision Voltage Reference, -40 to 125 degC, 8-pin SOIC (D), Green (RoHS & no Sb/Br); Manufacturer: Texas Instruments; Rating: Catalog; SubFamily: Series Voltage Reference; VI(Max)(V): 18; Temp Coeff(Max)(ppm/ degree C): 3; Initial Accuracy @ 25/deg C(%): 0.05; Iq(Max)(uA): 1000; VI(Min)(V): 4.296; Iout/Iz(Max)(mA): 10; VO(V): 4.096
U19 = CMP-0120501-1: Quad, 36-V, 1.2-MHz 3-mV offset voltage operational amplifier; Manufacturer: Texas Instruments; SizeZ_mm: 1.2mm; AEC Qualified: No; Gain Bandwidth: 1.2MHz; Input Bias Current: -0.01uA; Input Offset Voltage: 0.6mV; Max Dual Supply Voltage: 18V; Max Supply Voltage: 36V; Min Dual Supply Voltage: 2.5V; Min Supply Voltage: 5V; Nominal Supply Current: 240-350uA; Number Of Channels: 4; Output Current Per Channel: 20mA; Response Time: 4us; Standoff Height: 0.05mm; TaMax_C: +85°C; TaMin_C: -40°C; TJmax_C: +150°C; Voltage Gain: 100V/mV

## Sheet TIDA-010086E5_Cover.SchDoc
size 431 x 279 mm; Date: Not shown in title block; ApprovedBy: Not shown in title block; CheckedBy: Not shown in title block; Author: Not shown in title block; CompanyName: Not shown in title block; Engineer: Not shown in title block; Organization: Not shown in title block; Address1: Not shown in title block; Address2: Not shown in title block; Address3: Not shown in title block; Address4: Not shown in title block; DocumentNumber: 1; Revision: Use project parameter SCH_Rev; SheetNumber: 1; SheetTotal: 8; PageSetup: Record=PageOptions¦CenterHorizontal=True¦CenterVertical=True¦PrintScale=1.00¦XCorrection=1.00¦YCorrection=1.00¦PrintKind=0¦BorderSize=5000000¦LeftOffset=0¦BottomOffset=0¦Orientation=2¦PaperLength=1000¦PaperWidth=1000¦Scale=100¦PaperSource=15¦PrintQuality=600¦MediaType=1¦DitherType=10¦PaperKind=Letter¦PrintScaleMode=1
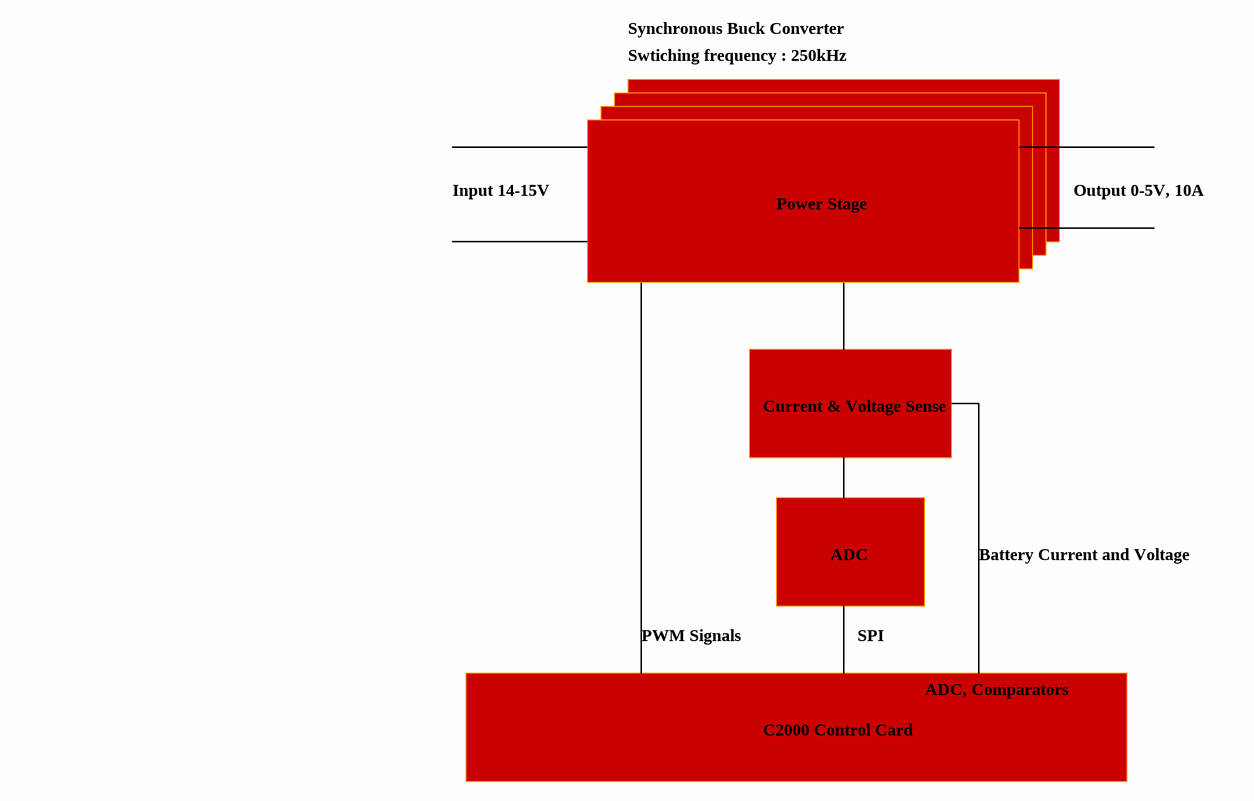
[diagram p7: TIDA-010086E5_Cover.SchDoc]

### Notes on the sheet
- Synchronous Buck Converter
- Swtiching frequency : 250kHz
- Input 14-15V
- Power Stage
- Output 0-5V, 10A
- Current & Voltage Sense
- ADC
- Battery Current and Voltage
- PWM Signals
- SPI
- ADC, Comparators
- C2000 Control Card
